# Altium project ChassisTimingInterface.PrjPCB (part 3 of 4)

## Sheet FPGA_ARTIX7.SchDoc: FPGA
size C; Organization: Altium Limited; Address1: L3, 12a Rodborough Rd; Address2: Frenchs Forest; Address3: NSW; Address4: Australia 2086; DocumentNumber: 7; SheetNumber: 6; SheetTotal: 12
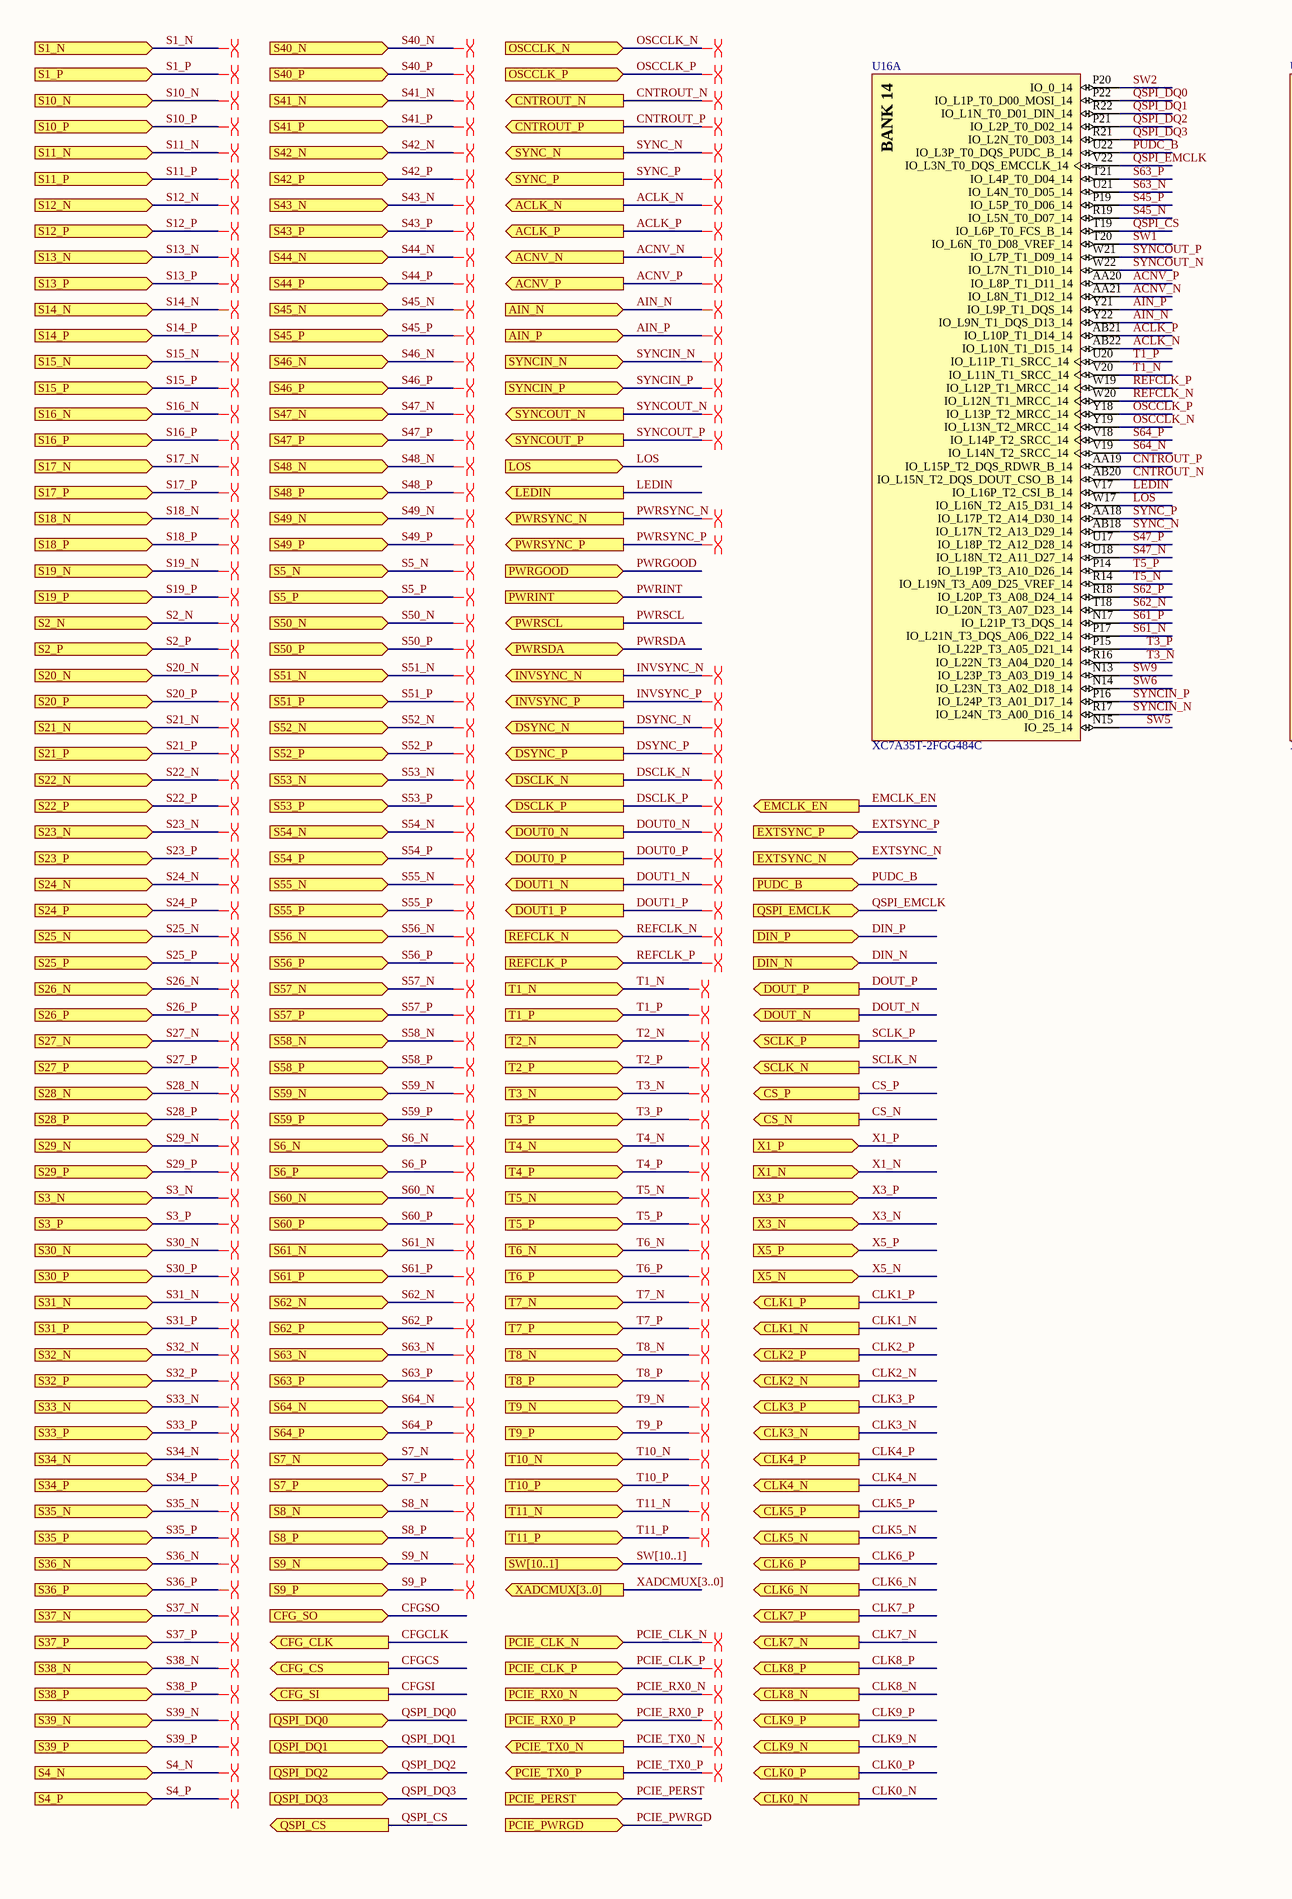
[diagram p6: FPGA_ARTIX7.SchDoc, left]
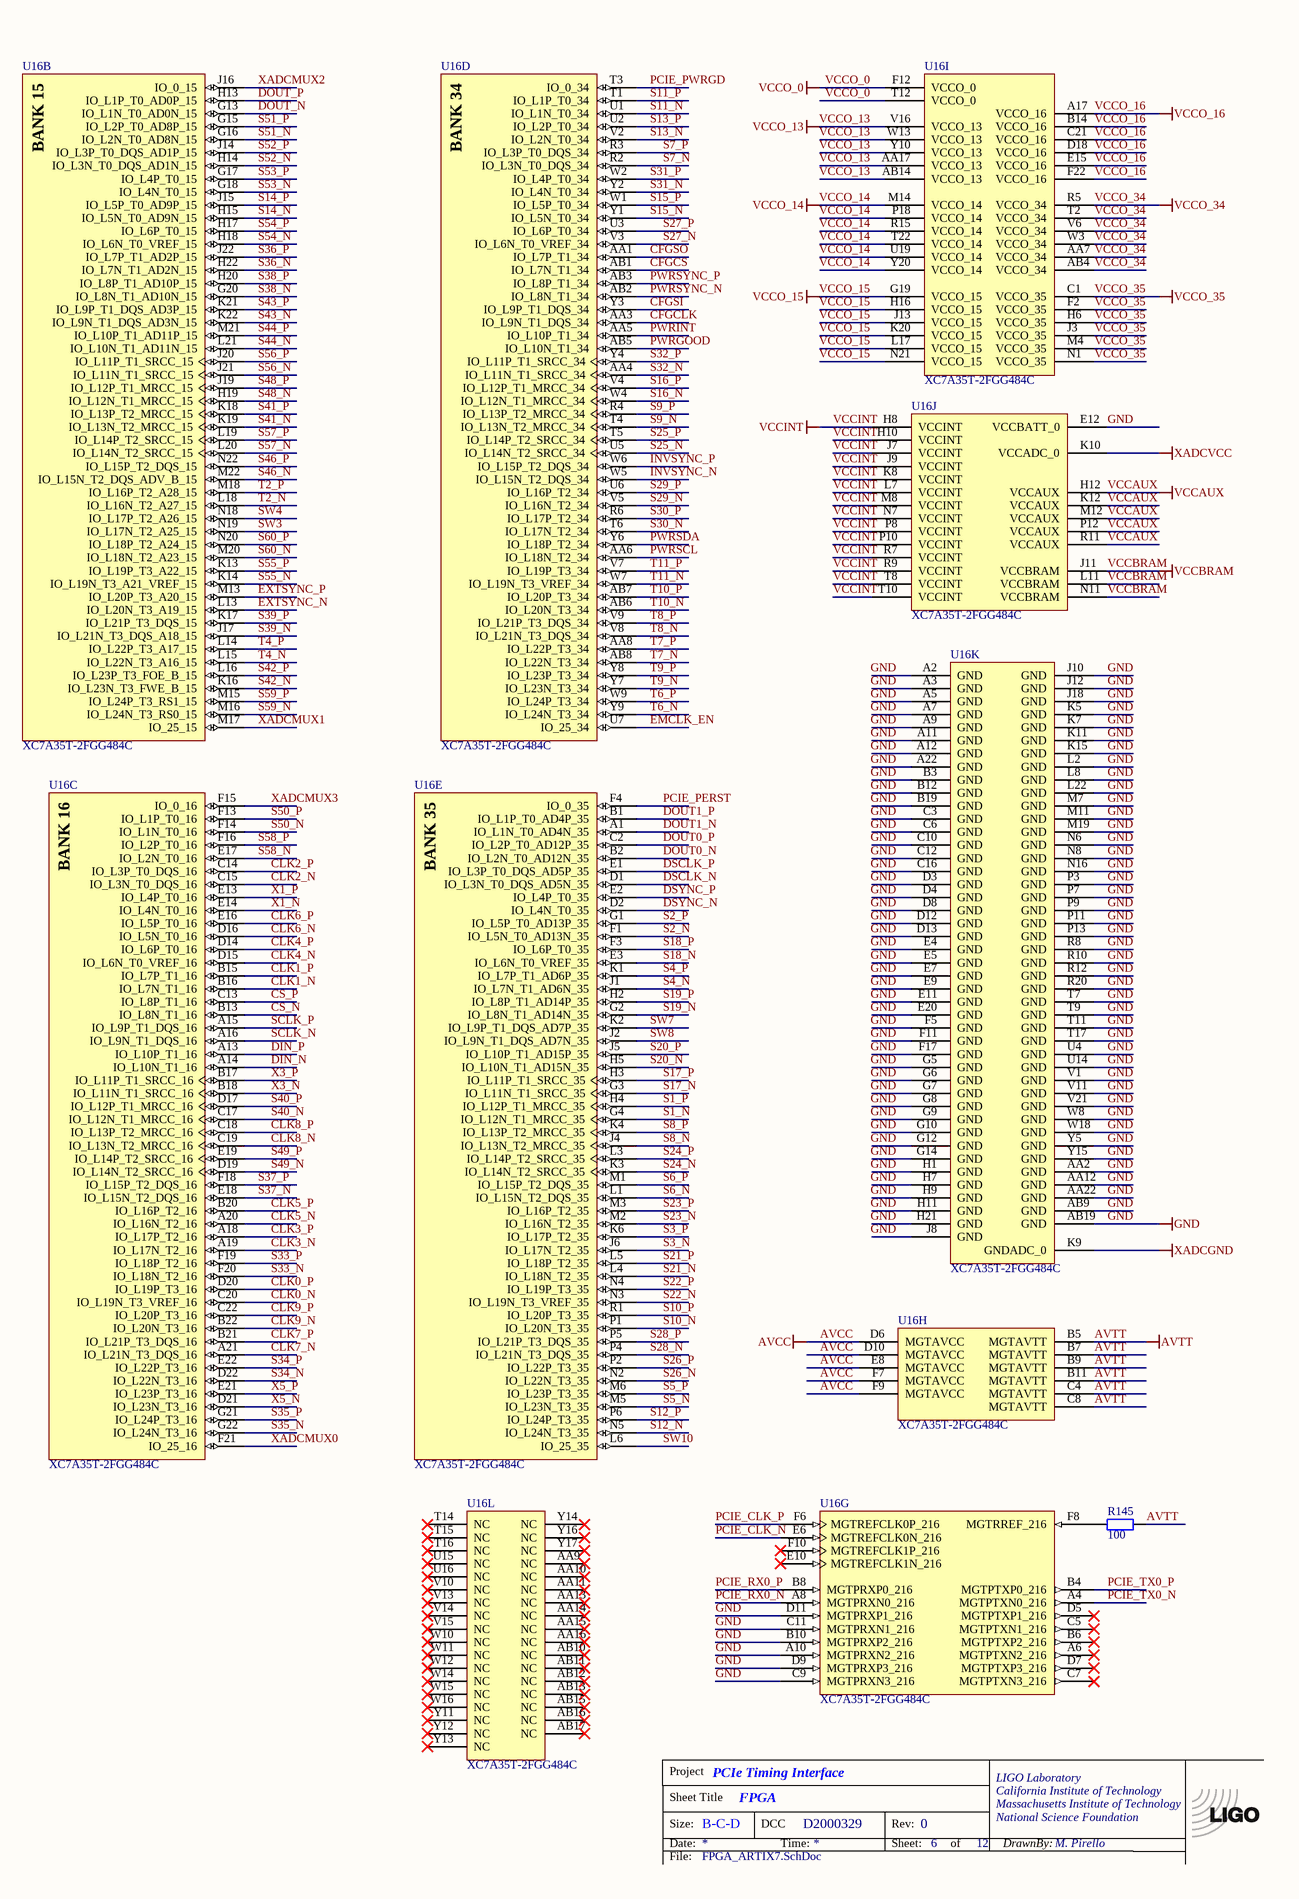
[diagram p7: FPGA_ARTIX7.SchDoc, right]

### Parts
(Parts that share a designator on the sheet are numbered #1, #2 ... from top to bottom, then left to right.)
*?#4  TitleBlock  (value not drawn)  (graphical)
R145  100  [CR1608-0603]
U16  XC7A35T-2FGG484C  [FGG484]  (parts A,B,C,D,E,G,H,I,J,K,L of 12)

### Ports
ACLK_N (out), ACLK_P (out), ACNV_N (out), ACNV_P (out), AIN_N (in), AIN_P (in), CFG_CLK (out), CFG_CS (out), CFG_SI (out), CFG_SO (in), CLK0_N (out), CLK0_P (out), CLK1_N (out), CLK1_P (out), CLK2_N (out), CLK2_P (out), CLK3_N (out), CLK3_P (out), CLK4_N (out), CLK4_P (out), CLK5_N (out), CLK5_P (out), CLK6_N (out), CLK6_P (out), CLK7_N (out), CLK7_P (out), CLK8_N (out), CLK8_P (out), CLK9_N (out), CLK9_P (out), CNTROUT_N (out), CNTROUT_P (out), CS_N (out), CS_P (out), DIN_N (in), DIN_P (in), DOUT0_N (out), DOUT0_P (out), DOUT1_N (out), DOUT1_P (out), DOUT_N (out), DOUT_P (out), DSCLK_N (out), DSCLK_P (out), DSYNC_N (out), DSYNC_P (out), EMCLK_EN (out), EXTSYNC_N (in), EXTSYNC_P (in), INVSYNC_N (out), INVSYNC_P (out), LEDIN (out), LOS (in), OSCCLK_N (in), OSCCLK_P (in), PCIE_CLK_N (in), PCIE_CLK_P (in), PCIE_PERST (in), PCIE_PWRGD (in), PCIE_RX0_N (in), PCIE_RX0_P (in), PCIE_TX0_N (out), PCIE_TX0_P (out), PUDC_B (in), PWRGOOD (in), PWRINT (in), PWRSCL (out), PWRSDA (bidir), PWRSYNC_N (out), PWRSYNC_P (out), QSPI_CS (out), QSPI_DQ0 (in), QSPI_DQ1 (in), QSPI_DQ2 (in), QSPI_DQ3 (in), QSPI_EMCLK (in), REFCLK_N (in), REFCLK_P (in), S1_N (in), S1_P (in), S2_N (in), S2_P (in), S3_N (in), S3_P (in), S4_N (in), S4_P (in), S5_N (in), S5_P (in), S6_N (in), S6_P (in), S7_N (in), S7_P (in), S8_N (in), S8_P (in), S9_N (in), S9_P (in), S10_N (in), S10_P (in), S11_N (in), S11_P (in), S12_N (in), S12_P (in), S13_N (in), S13_P (in), S14_N (in), S14_P (in), S15_N (in), S15_P (in), S16_N (in), S16_P (in), S17_N (in), S17_P (in), S18_N (in), S18_P (in), S19_N (in), S19_P (in), S20_N (in), S20_P (in), S21_N (in), S21_P (in), S22_N (in), S22_P (in), S23_N (in), S23_P (in), S24_N (in), S24_P (in), S25_N (in), S25_P (in), S26_N (in), S26_P (in), S27_N (in), S27_P (in), S28_N (in), S28_P (in), S29_N (in), S29_P (in), S30_N (in), S30_P (in), S31_N (in), S31_P (in), S32_N (in), S32_P (in), S33_N (in), S33_P (in), S34_N (in), S34_P (in), S35_N (in), S35_P (in), S36_N (in), S36_P (in), S37_N (in), S37_P (in), S38_N (in), S38_P (in), S39_N (in), S39_P (in), S40_N (in), S40_P (in), S41_N (in), S41_P (in), S42_N (in), S42_P (in), S43_N (in), S43_P (in), S44_N (in), S44_P (in), S45_N (in), S45_P (in), S46_N (in), S46_P (in), S47_N (in), S47_P (in), S48_N (in), S48_P (in), S49_N (in), S49_P (in), S50_N (in), S50_P (in), S51_N (in), S51_P (in), S52_N (in), S52_P (in), S53_N (in), S53_P (in), S54_N (in), S54_P (in), S55_N (in), S55_P (in), S56_N (in), S56_P (in), S57_N (in), S57_P (in), S58_N (in), S58_P (in), S59_N (in), S59_P (in), S60_N (in), S60_P (in), S61_N (in), S61_P (in), S62_N (in), S62_P (in), S63_N (in), S63_P (in), S64_N (in), S64_P (in), SCLK_N (out), SCLK_P (out), SW[10..1] (in), SYNC_N (out), SYNC_P (out), SYNCIN_N (in), SYNCIN_P (in), SYNCOUT_N (out), SYNCOUT_P (out), T1_N (in), T1_P (in), T2_N (in), T2_P (in), T3_N (in), T3_P (in), T4_N (in), T4_P (in), T5_N (in), T5_P (in), T6_N (in), T6_P (in), T7_N (in), T7_P (in), T8_N (in), T8_P (in), T9_N (in), T9_P (in), T10_N (in), T10_P (in), T11_N (in), T11_P (in), X1_N (in), X1_P (in), X3_N (in), X3_P (in), X5_N (in), X5_P (in), XADCMUX[3..0] (out)

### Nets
AVCC: U16.D6(MGTAVCC) U16.D10(MGTAVCC) U16.E8(MGTAVCC) U16.F7(MGTAVCC) U16.F9(MGTAVCC)
AVTT: R145.2 U16.B5(MGTAVTT) U16.B7(MGTAVTT) U16.B9(MGTAVTT) U16.B11(MGTAVTT) U16.C4(MGTAVTT) U16.C8(MGTAVTT)
GND: U16.A2(GND) U16.A3(GND) U16.A5(GND) U16.A7(GND) U16.A9(GND) U16.A10(MGTPRXN2_216) U16.A11(GND) U16.A12(GND) U16.A22(GND) U16.AA2(GND) U16.AA12(GND) U16.AA22(GND) U16.AB9(GND) U16.AB19(GND) U16.B3(GND) U16.B10(MGTPRXP2_216) U16.B12(GND) U16.B19(GND) U16.C3(GND) U16.C6(GND) U16.C9(MGTPRXN3_216) U16.C10(GND) U16.C11(MGTPRXN1_216) U16.C12(GND) U16.C16(GND) U16.D3(GND) U16.D4(GND) U16.D8(GND) U16.D9(MGTPRXP3_216) U16.D11(MGTPRXP1_216) U16.D12(GND) U16.D13(GND) U16.E4(GND) U16.E5(GND) U16.E7(GND) U16.E9(GND) U16.E11(GND) U16.E12(VCCBATT_0) U16.E20(GND) U16.F5(GND) U16.F11(GND) U16.F17(GND) U16.G5(GND) U16.G6(GND) U16.G7(GND) U16.G8(GND) U16.G9(GND) U16.G10(GND) U16.G12(GND) U16.G14(GND) U16.H1(GND) U16.H7(GND) U16.H9(GND) U16.H11(GND) U16.H21(GND) U16.J8(GND) U16.J10(GND) U16.J12(GND) U16.J18(GND) U16.K5(GND) U16.K7(GND) U16.K11(GND) U16.K15(GND) U16.L2(GND) U16.L8(GND) U16.L22(GND) U16.M7(GND) U16.M11(GND) U16.M19(GND) U16.N6(GND) U16.N8(GND) U16.N16(GND) U16.P3(GND) U16.P7(GND) U16.P9(GND) U16.P11(GND) U16.P13(GND) U16.R8(GND) U16.R10(GND) U16.R12(GND) U16.R20(GND) U16.T7(GND) U16.T9(GND) U16.T11(GND) U16.T17(GND) U16.U4(GND) U16.U14(GND) U16.V1(GND) U16.V11(GND) U16.V21(GND) U16.W8(GND) U16.W18(GND) U16.Y5(GND) U16.Y15(GND)
VCCAUX: U16.H12(VCCAUX) U16.K12(VCCAUX) U16.M12(VCCAUX) U16.P12(VCCAUX) U16.R11(VCCAUX)  [project net VCC1V8]
VCCINT: U16.H8(VCCINT) U16.H10(VCCINT) U16.J7(VCCINT) U16.J9(VCCINT) U16.J11(VCCBRAM) U16.K8(VCCINT) U16.L7(VCCINT) U16.L11(VCCBRAM) U16.M8(VCCINT) U16.N7(VCCINT) U16.N11(VCCBRAM) U16.P8(VCCINT) U16.P10(VCCINT) U16.R7(VCCINT) U16.R9(VCCINT) U16.T8(VCCINT) U16.T10(VCCINT)  [also labelled VCCBRAM]
VCCO_0: U16.A17(VCCO_16) U16.AA7(VCCO_34) U16.AA17(VCCO_13) U16.AB4(VCCO_34) U16.AB14(VCCO_13) U16.B14(VCCO_16) U16.C1(VCCO_35) U16.C21(VCCO_16) U16.D18(VCCO_16) U16.E15(VCCO_16) U16.F2(VCCO_35) U16.F12(VCCO_0) U16.F22(VCCO_16) U16.G19(VCCO_15) U16.H6(VCCO_35) U16.H16(VCCO_15) U16.J3(VCCO_35) U16.J13(VCCO_15) U16.K20(VCCO_15) U16.L17(VCCO_15) U16.M4(VCCO_35) U16.M14(VCCO_14) U16.N1(VCCO_35) U16.N21(VCCO_15) U16.P18(VCCO_14) U16.R5(VCCO_34) U16.R15(VCCO_14) U16.T2(VCCO_34) U16.T12(VCCO_0) U16.T22(VCCO_14) U16.U19(VCCO_14) U16.V6(VCCO_34) U16.V16(VCCO_13) U16.W3(VCCO_34) U16.W13(VCCO_13) U16.Y10(VCCO_13) U16.Y20(VCCO_14)  [also labelled VCCO_13, VCCO_14, VCCO_15, VCCO_16, VCCO_34, VCCO_35]  [project net VDD]
XADCGND: U16.K9(GNDADC_0)
XADCVCC: U16.K10(VCCADC_0)
ACLK_N: U16.AB22(IO_L10N_T1_D15_14) ; port ACLK_N  [project net CLOCK.ACLK_N]
ACLK_P: U16.AB21(IO_L10P_T1_D14_14) ; port ACLK_P  [project net CLOCK.ACLK_P]
ACNV_N: U16.AA21(IO_L8N_T1_D12_14) ; port ACNV_N  [project net CLOCK.ACNV_N]
ACNV_P: U16.AA20(IO_L8P_T1_D11_14) ; port ACNV_P  [project net CLOCK.ACNV_P]
AIN_N: U16.Y22(IO_L9N_T1_DQS_D13_14) ; port AIN_N  [project net CLOCK.AIN_N]
AIN_P: U16.Y21(IO_L9P_T1_DQS_14) ; port AIN_P  [project net CLOCK.AIN_P]
CFGCLK: U16.AA3(IO_L9N_T1_DQS_34) ; port CFG_CLK  [project net CFG_CLK]
CFGCS: U16.AB1(IO_L7N_T1_34) ; port CFG_CS  [project net CFG_CS]
CFGSI: U16.Y3(IO_L9P_T1_DQS_34) ; port CFG_SI  [project net CFG_SI]
CFGSO: U16.AA1(IO_L7P_T1_34) ; port CFG_SO  [project net CFG_SO]
CLK0_N: U16.C20(IO_L19N_T3_VREF_16) ; port CLK0_N  [project net BACKPLANE.CLK0_N]
CLK0_P: U16.D20(IO_L19P_T3_16) ; port CLK0_P  [project net BACKPLANE.CLK0_P]
CLK1_N: U16.B16(IO_L7N_T1_16) ; port CLK1_N  [project net BACKPLANE.CLK1_N]
CLK1_P: U16.B15(IO_L7P_T1_16) ; port CLK1_P  [project net BACKPLANE.CLK1_P]
CLK2_N: U16.C15(IO_L3N_T0_DQS_16) ; port CLK2_N  [project net BACKPLANE.CLK2_N]
CLK2_P: U16.C14(IO_L3P_T0_DQS_16) ; port CLK2_P  [project net BACKPLANE.CLK2_P]
CLK3_N: U16.A19(IO_L17N_T2_16) ; port CLK3_N  [project net BACKPLANE.CLK3_N]
CLK3_P: U16.A18(IO_L17P_T2_16) ; port CLK3_P  [project net BACKPLANE.CLK3_P]
CLK4_N: U16.D15(IO_L6N_T0_VREF_16) ; port CLK4_N  [project net BACKPLANE.CLK4_N]
CLK4_P: U16.D14(IO_L6P_T0_16) ; port CLK4_P  [project net BACKPLANE.CLK4_P]
CLK5_N: U16.A20(IO_L16N_T2_16) ; port CLK5_N  [project net BACKPLANE.CLK5_N]
CLK5_P: U16.B20(IO_L16P_T2_16) ; port CLK5_P  [project net BACKPLANE.CLK5_P]
CLK6_N: U16.D16(IO_L5N_T0_16) ; port CLK6_N  [project net BACKPLANE.CLK6_N]
CLK6_P: U16.E16(IO_L5P_T0_16) ; port CLK6_P  [project net BACKPLANE.CLK6_P]
CLK7_N: U16.A21(IO_L21N_T3_DQS_16) ; port CLK7_N  [project net BACKPLANE.CLK7_N]
CLK7_P: U16.B21(IO_L21P_T3_DQS_16) ; port CLK7_P  [project net BACKPLANE.CLK7_P]
CLK8_N: U16.C19(IO_L13N_T2_MRCC_16) ; port CLK8_N  [project net BACKPLANE.CLK8_N]
CLK8_P: U16.C18(IO_L13P_T2_MRCC_16) ; port CLK8_P  [project net BACKPLANE.CLK8_P]
CLK9_N: U16.B22(IO_L20N_T3_16) ; port CLK9_N  [project net BACKPLANE.CLK9_N]
CLK9_P: U16.C22(IO_L20P_T3_16) ; port CLK9_P  [project net BACKPLANE.CLK9_P]
CNTROUT_N: U16.AB20(IO_L15N_T2_DQS_DOUT_CSO_B_14) ; port CNTROUT_N  [project net CLOCK.CNTROUT_N]
CNTROUT_P: U16.AA19(IO_L15P_T2_DQS_RDWR_B_14) ; port CNTROUT_P  [project net CLOCK.CNTROUT_P]
CS_N: U16.B13(IO_L8N_T1_16) ; port CS_N  [project net BACKPLANE.CS_N]
CS_P: U16.C13(IO_L8P_T1_16) ; port CS_P  [project net BACKPLANE.CS_P]
DIN_N: U16.A14(IO_L10N_T1_16) ; port DIN_N  [project net BACKPLANE.DIN_N]
DIN_P: U16.A13(IO_L10P_T1_16) ; port DIN_P  [project net BACKPLANE.DIN_P]
DOUT0_N: U16.B2(IO_L2N_T0_AD12N_35) ; port DOUT0_N  [project net DAC_REF.DOUT0_N]
DOUT0_P: U16.C2(IO_L2P_T0_AD12P_35) ; port DOUT0_P  [project net DAC_REF.DOUT0_P]
DOUT1_N: U16.A1(IO_L1N_T0_AD4N_35) ; port DOUT1_N  [project net DAC_REF.DOUT1_N]
DOUT1_P: U16.B1(IO_L1P_T0_AD4P_35) ; port DOUT1_P  [project net DAC_REF.DOUT1_P]
DOUT_N: U16.G13(IO_L1N_T0_AD0N_15) ; port DOUT_N  [project net BACKPLANE.DOUT_N]
DOUT_P: U16.H13(IO_L1P_T0_AD0P_15) ; port DOUT_P  [project net BACKPLANE.DOUT_P]
DSCLK_N: U16.D1(IO_L3N_T0_DQS_AD5N_35) ; port DSCLK_N  [project net DAC_REF.DSCLK_N]
DSCLK_P: U16.E1(IO_L3P_T0_DQS_AD5P_35) ; port DSCLK_P  [project net DAC_REF.DSCLK_P]
DSYNC_N: U16.D2(IO_L4N_T0_35) ; port DSYNC_N  [project net DAC_REF.DSYNC_N]
DSYNC_P: U16.E2(IO_L4P_T0_35) ; port DSYNC_P  [project net DAC_REF.DSYNC_P]
EMCLK_EN: U16.U7(IO_25_34) ; port EMCLK_EN  [project net SQSPI.EMCLK_EN]
EXTSYNC_N: U16.L13(IO_L20N_T3_A19_15) ; port EXTSYNC_N  [project net EXT_SYNC.EXTSYNC_N]
EXTSYNC_P: U16.M13(IO_L20P_T3_A20_15) ; port EXTSYNC_P  [project net EXT_SYNC.EXTSYNC_P]
INVSYNC_N: U16.W5(IO_L15N_T2_DQS_34) ; port INVSYNC_N  [project net DAC_REF.INVSYNC_N]
INVSYNC_P: U16.W6(IO_L15P_T2_DQS_34) ; port INVSYNC_P  [project net DAC_REF.INVSYNC_P]
LEDIN: U16.V17(IO_L16P_T2_CSI_B_14) ; port LEDIN  [project net SFPIN.LEDIN]
LOS: U16.W17(IO_L16N_T2_A15_D31_14) ; port LOS  [project net SFPIN.LOS]
OSCCLK_N: U16.Y19(IO_L13N_T2_MRCC_14) ; port OSCCLK_N  [project net CLOCK.OSCCLK_N]
OSCCLK_P: U16.Y18(IO_L13P_T2_MRCC_14) ; port OSCCLK_P  [project net CLOCK.OSCCLK_P]
PCIE_CLK_N: U16.E6(MGTREFCLK0N_216) ; port PCIE_CLK_N  [project net PCIE.PCIE_CLK_N]
PCIE_CLK_P: U16.F6(MGTREFCLK0P_216) ; port PCIE_CLK_P  [project net PCIE.PCIE_CLK_P]
PCIE_PERST: U16.F4(IO_0_35) ; port PCIE_PERST  [project net PCIE.PCIE_PERST]
PCIE_PWRGD: U16.T3(IO_0_34) ; port PCIE_PWRGD  [project net PCIE.PCIE_PWRGD]
PCIE_RX0_N: U16.A8(MGTPRXN0_216) ; port PCIE_RX0_N  [project net PCIE.PCIE_RX0_N]
PCIE_RX0_P: U16.B8(MGTPRXP0_216) ; port PCIE_RX0_P  [project net PCIE.PCIE_RX0_P]
PCIE_TX0_N: U16.A4(MGTPTXN0_216) ; port PCIE_TX0_N  [project net PCIE.PCIE_TX0_N]
PCIE_TX0_P: U16.B4(MGTPTXP0_216) ; port PCIE_TX0_P  [project net PCIE.PCIE_TX0_P]
PUDC_B: U16.U22(IO_L3P_T0_DQS_PUDC_B_14) ; port PUDC_B  [project net SQSPI.PUDC_B]
PWRGOOD: U16.AB5(IO_L10N_T1_34) ; port PWRGOOD  [project net POWER.PWRGOOD]
PWRINT: U16.AA5(IO_L10P_T1_34) ; port PWRINT  [project net POWER.PWRINT]
PWRSCL: U16.AA6(IO_L18N_T2_34) ; port PWRSCL  [project net POWER.PWRSCL]
PWRSDA: U16.Y6(IO_L18P_T2_34) ; port PWRSDA  [project net POWER.PWRSDA]
PWRSYNC_N: U16.AB2(IO_L8N_T1_34) ; port PWRSYNC_N  [project net POWER.PWRSYNC_N]
PWRSYNC_P: U16.AB3(IO_L8P_T1_34) ; port PWRSYNC_P  [project net POWER.PWRSYNC_P]
QSPI_CS: U16.T19(IO_L6P_T0_FCS_B_14) ; port QSPI_CS  [project net SQSPI.QSPI_CS]
QSPI_DQ0: U16.P22(IO_L1P_T0_D00_MOSI_14) ; port QSPI_DQ0  [project net SQSPI.QSPI_DQ0]
QSPI_DQ1: U16.R22(IO_L1N_T0_D01_DIN_14) ; port QSPI_DQ1  [project net SQSPI.QSPI_DQ1]
QSPI_DQ2: U16.P21(IO_L2P_T0_D02_14) ; port QSPI_DQ2  [project net SQSPI.QSPI_DQ2]
QSPI_DQ3: U16.R21(IO_L2N_T0_D03_14) ; port QSPI_DQ3  [project net SQSPI.QSPI_DQ3]
QSPI_EMCLK: U16.V22(IO_L3N_T0_DQS_EMCCLK_14) ; port QSPI_EMCLK  [project net SQSPI.QSPI_EMCLK]
REFCLK_N: U16.W20(IO_L12N_T1_MRCC_14) ; port REFCLK_N  [project net DAC_REF.REFCLK_N]
REFCLK_P: U16.W19(IO_L12P_T1_MRCC_14) ; port REFCLK_P  [project net DAC_REF.REFCLK_P]
S1_N: U16.G4(IO_L12N_T1_MRCC_35) ; port S1_N  [project net S1_16.S1_N]
S1_P: U16.H4(IO_L12P_T1_MRCC_35) ; port S1_P  [project net S1_16.S1_P]
S2_N: U16.F1(IO_L5N_T0_AD13N_35) ; port S2_N  [project net S1_16.S2_N]
S2_P: U16.G1(IO_L5P_T0_AD13P_35) ; port S2_P  [project net S1_16.S2_P]
S3_N: U16.J6(IO_L17N_T2_35) ; port S3_N  [project net S1_16.S3_N]
S3_P: U16.K6(IO_L17P_T2_35) ; port S3_P  [project net S1_16.S3_P]
S4_N: U16.J1(IO_L7N_T1_AD6N_35) ; port S4_N  [project net S1_16.S4_N]
S4_P: U16.K1(IO_L7P_T1_AD6P_35) ; port S4_P  [project net S1_16.S4_P]
S5_N: U16.M5(IO_L23N_T3_35) ; port S5_N  [project net S1_16.S5_N]
S5_P: U16.M6(IO_L23P_T3_35) ; port S5_P  [project net S1_16.S5_P]
S6_N: U16.L1(IO_L15N_T2_DQS_35) ; port S6_N  [project net S1_16.S6_N]
S6_P: U16.M1(IO_L15P_T2_DQS_35) ; port S6_P  [project net S1_16.S6_P]
S7_N: U16.R2(IO_L3N_T0_DQS_34) ; port S7_N  [project net S1_16.S7_N]
S7_P: U16.R3(IO_L3P_T0_DQS_34) ; port S7_P  [project net S1_16.S7_P]
S8_N: U16.J4(IO_L13N_T2_MRCC_35) ; port S8_N  [project net S1_16.S8_N]
S8_P: U16.K4(IO_L13P_T2_MRCC_35) ; port S8_P  [project net S1_16.S8_P]
S9_N: U16.T4(IO_L13N_T2_MRCC_34) ; port S9_N  [project net S1_16.S9_N]
S9_P: U16.R4(IO_L13P_T2_MRCC_34) ; port S9_P  [project net S1_16.S9_P]
S10_N: U16.P1(IO_L20N_T3_35) ; port S10_N
S10_P: U16.R1(IO_L20P_T3_35) ; port S10_P
S11_N: U16.U1(IO_L1N_T0_34) ; port S11_N
S11_P: U16.T1(IO_L1P_T0_34) ; port S11_P
S12_N: U16.N5(IO_L24N_T3_35) ; port S12_N
S12_P: U16.P6(IO_L24P_T3_35) ; port S12_P
S13_N: U16.V2(IO_L2N_T0_34) ; port S13_N
S13_P: U16.U2(IO_L2P_T0_34) ; port S13_P
S14_N: U16.H15(IO_L5N_T0_AD9N_15) ; port S14_N
S14_P: U16.J15(IO_L5P_T0_AD9P_15) ; port S14_P
S15_N: U16.Y1(IO_L5N_T0_34) ; port S15_N
S15_P: U16.W1(IO_L5P_T0_34) ; port S15_P
S16_N: U16.W4(IO_L12N_T1_MRCC_34) ; port S16_N
S16_P: U16.V4(IO_L12P_T1_MRCC_34) ; port S16_P
S17_N: U16.G3(IO_L11N_T1_SRCC_35) ; port S17_N  [project net S17_32.S17_N]
S17_P: U16.H3(IO_L11P_T1_SRCC_35) ; port S17_P  [project net S17_32.S17_P]
S18_N: U16.E3(IO_L6N_T0_VREF_35) ; port S18_N  [project net S17_32.S18_N]
S18_P: U16.F3(IO_L6P_T0_35) ; port S18_P  [project net S17_32.S18_P]
S19_N: U16.G2(IO_L8N_T1_AD14N_35) ; port S19_N  [project net S17_32.S19_N]
S19_P: U16.H2(IO_L8P_T1_AD14P_35) ; port S19_P  [project net S17_32.S19_P]
S20_N: U16.H5(IO_L10N_T1_AD15N_35) ; port S20_N  [project net S17_32.S20_N]
S20_P: U16.J5(IO_L10P_T1_AD15P_35) ; port S20_P  [project net S17_32.S20_P]
S21_N: U16.L4(IO_L18N_T2_35) ; port S21_N  [project net S17_32.S21_N]
S21_P: U16.L5(IO_L18P_T2_35) ; port S21_P  [project net S17_32.S21_P]
S22_N: U16.N3(IO_L19N_T3_VREF_35) ; port S22_N  [project net S17_32.S22_N]
S22_P: U16.N4(IO_L19P_T3_35) ; port S22_P  [project net S17_32.S22_P]
S23_N: U16.M2(IO_L16N_T2_35) ; port S23_N  [project net S17_32.S23_N]
S23_P: U16.M3(IO_L16P_T2_35) ; port S23_P  [project net S17_32.S23_P]
S24_N: U16.K3(IO_L14N_T2_SRCC_35) ; port S24_N  [project net S17_32.S24_N]
S24_P: U16.L3(IO_L14P_T2_SRCC_35) ; port S24_P  [project net S17_32.S24_P]
S25_N: U16.U5(IO_L14N_T2_SRCC_34) ; port S25_N  [project net S17_32.S25_N]
S25_P: U16.T5(IO_L14P_T2_SRCC_34) ; port S25_P  [project net S17_32.S25_P]
S26_N: U16.N2(IO_L22N_T3_35) ; port S26_N  [project net S17_32.S26_N]
S26_P: U16.P2(IO_L22P_T3_35) ; port S26_P  [project net S17_32.S26_P]
S27_N: U16.V3(IO_L6N_T0_VREF_34) ; port S27_N  [project net S17_32.S27_N]
S27_P: U16.U3(IO_L6P_T0_34) ; port S27_P  [project net S17_32.S27_P]
S28_N: U16.P4(IO_L21N_T3_DQS_35) ; port S28_N  [project net S17_32.S28_N]
S28_P: U16.P5(IO_L21P_T3_DQS_35) ; port S28_P  [project net S17_32.S28_P]
S29_N: U16.V5(IO_L16N_T2_34) ; port S29_N  [project net S17_32.S29_N]
S29_P: U16.U6(IO_L16P_T2_34) ; port S29_P  [project net S17_32.S29_P]
S30_N: U16.T6(IO_L17N_T2_34) ; port S30_N  [project net S17_32.S30_N]
S30_P: U16.R6(IO_L17P_T2_34) ; port S30_P  [project net S17_32.S30_P]
S31_N: U16.Y2(IO_L4N_T0_34) ; port S31_N  [project net S17_32.S31_N]
S31_P: U16.W2(IO_L4P_T0_34) ; port S31_P  [project net S17_32.S31_P]
S32_N: U16.AA4(IO_L11N_T1_SRCC_34) ; port S32_N  [project net S17_32.S32_N]
S32_P: U16.Y4(IO_L11P_T1_SRCC_34) ; port S32_P  [project net S17_32.S32_P]
S33_N: U16.F20(IO_L18N_T2_16) ; port S33_N  [project net S33_48.S33_N]
S33_P: U16.F19(IO_L18P_T2_16) ; port S33_P  [project net S33_48.S33_P]
S34_N: U16.D22(IO_L22N_T3_16) ; port S34_N  [project net S33_48.S34_N]
S34_P: U16.E22(IO_L22P_T3_16) ; port S34_P  [project net S33_48.S34_P]
S35_N: U16.G22(IO_L24N_T3_16) ; port S35_N  [project net S33_48.S35_N]
S35_P: U16.G21(IO_L24P_T3_16) ; port S35_P  [project net S33_48.S35_P]
S36_N: U16.H22(IO_L7N_T1_AD2N_15) ; port S36_N  [project net S33_48.S36_N]
S36_P: U16.J22(IO_L7P_T1_AD2P_15) ; port S36_P  [project net S33_48.S36_P]
S37_N: U16.E18(IO_L15N_T2_DQS_16) ; port S37_N  [project net S33_48.S37_N]
S37_P: U16.F18(IO_L15P_T2_DQS_16) ; port S37_P  [project net S33_48.S37_P]
S38_N: U16.G20(IO_L8N_T1_AD10N_15) ; port S38_N  [project net S33_48.S38_N]
S38_P: U16.H20(IO_L8P_T1_AD10P_15) ; port S38_P  [project net S33_48.S38_P]
S39_N: U16.J17(IO_L21N_T3_DQS_A18_15) ; port S39_N  [project net S33_48.S39_N]
S39_P: U16.K17(IO_L21P_T3_DQS_15) ; port S39_P  [project net S33_48.S39_P]
S40_N: U16.C17(IO_L12N_T1_MRCC_16) ; port S40_N  [project net S33_48.S40_N]
S40_P: U16.D17(IO_L12P_T1_MRCC_16) ; port S40_P  [project net S33_48.S40_P]
S41_N: U16.K19(IO_L13N_T2_MRCC_15) ; port S41_N  [project net S33_48.S41_N]
S41_P: U16.K18(IO_L13P_T2_MRCC_15) ; port S41_P  [project net S33_48.S41_P]
S42_N: U16.K16(IO_L23N_T3_FWE_B_15) ; port S42_N  [project net S33_48.S42_N]
S42_P: U16.L16(IO_L23P_T3_FOE_B_15) ; port S42_P  [project net S33_48.S42_P]
S43_N: U16.K22(IO_L9N_T1_DQS_AD3N_15) ; port S43_N  [project net S33_48.S43_N]
S43_P: U16.K21(IO_L9P_T1_DQS_AD3P_15) ; port S43_P  [project net S33_48.S43_P]
S44_N: U16.L21(IO_L10N_T1_AD11N_15) ; port S44_N  [project net S33_48.S44_N]
S44_P: U16.M21(IO_L10P_T1_AD11P_15) ; port S44_P  [project net S33_48.S44_P]
S45_N: U16.R19(IO_L5N_T0_D07_14) ; port S45_N  [project net S33_48.S45_N]
S45_P: U16.P19(IO_L5P_T0_D06_14) ; port S45_P  [project net S33_48.S45_P]
S46_N: U16.M22(IO_L15N_T2_DQS_ADV_B_15) ; port S46_N  [project net S33_48.S46_N]
S46_P: U16.N22(IO_L15P_T2_DQS_15) ; port S46_P  [project net S33_48.S46_P]
S47_N: U16.U18(IO_L18N_T2_A11_D27_14) ; port S47_N  [project net S33_48.S47_N]
S47_P: U16.U17(IO_L18P_T2_A12_D28_14) ; port S47_P  [project net S33_48.S47_P]
S48_N: U16.H19(IO_L12N_T1_MRCC_15) ; port S48_N  [project net S33_48.S48_N]
S48_P: U16.J19(IO_L12P_T1_MRCC_15) ; port S48_P  [project net S33_48.S48_P]
S49_N: U16.D19(IO_L14N_T2_SRCC_16) ; port S49_N  [project net S49_64.S49_N]
S49_P: U16.E19(IO_L14P_T2_SRCC_16) ; port S49_P  [project net S49_64.S49_P]
S50_N: U16.F14(IO_L1N_T0_16) ; port S50_N  [project net S49_64.S50_N]
S50_P: U16.F13(IO_L1P_T0_16) ; port S50_P  [project net S49_64.S50_P]
S51_N: U16.G16(IO_L2N_T0_AD8N_15) ; port S51_N  [project net S49_64.S51_N]
S51_P: U16.G15(IO_L2P_T0_AD8P_15) ; port S51_P  [project net S49_64.S51_P]
S52_N: U16.H14(IO_L3N_T0_DQS_AD1N_15) ; port S52_N  [project net S49_64.S52_N]
S52_P: U16.J14(IO_L3P_T0_DQS_AD1P_15) ; port S52_P  [project net S49_64.S52_P]
S53_N: U16.G18(IO_L4N_T0_15) ; port S53_N  [project net S49_64.S53_N]
S53_P: U16.G17(IO_L4P_T0_15) ; port S53_P  [project net S49_64.S53_P]
S54_N: U16.H18(IO_L6N_T0_VREF_15) ; port S54_N  [project net S49_64.S54_N]
S54_P: U16.H17(IO_L6P_T0_15) ; port S54_P  [project net S49_64.S54_P]
S55_N: U16.K14(IO_L19N_T3_A21_VREF_15) ; port S55_N  [project net S49_64.S55_N]
S55_P: U16.K13(IO_L19P_T3_A22_15) ; port S55_P  [project net S49_64.S55_P]
S56_N: U16.J21(IO_L11N_T1_SRCC_15) ; port S56_N  [project net S49_64.S56_N]
S56_P: U16.J20(IO_L11P_T1_SRCC_15) ; port S56_P  [project net S49_64.S56_P]
S57_N: U16.L20(IO_L14N_T2_SRCC_15) ; port S57_N  [project net S49_64.S57_N]
S57_P: U16.L19(IO_L14P_T2_SRCC_15) ; port S57_P  [project net S49_64.S57_P]
S58_N: U16.E17(IO_L2N_T0_16) ; port S58_N  [project net S49_64.S58_N]
S58_P: U16.F16(IO_L2P_T0_16) ; port S58_P  [project net S49_64.S58_P]
S59_N: U16.M16(IO_L24N_T3_RS0_15) ; port S59_N  [project net S49_64.S59_N]
S59_P: U16.M15(IO_L24P_T3_RS1_15) ; port S59_P  [project net S49_64.S59_P]
S60_N: U16.M20(IO_L18N_T2_A23_15) ; port S60_N  [project net S49_64.S60_N]
S60_P: U16.N20(IO_L18P_T2_A24_15) ; port S60_P  [project net S49_64.S60_P]
S61_N: U16.P17(IO_L21N_T3_DQS_A06_D22_14) ; port S61_N  [project net S49_64.S61_N]
S61_P: U16.N17(IO_L21P_T3_DQS_14) ; port S61_P  [project net S49_64.S61_P]
S62_N: U16.T18(IO_L20N_T3_A07_D23_14) ; port S62_N  [project net S49_64.S62_N]
S62_P: U16.R18(IO_L20P_T3_A08_D24_14) ; port S62_P  [project net S49_64.S62_P]
S63_N: U16.U21(IO_L4N_T0_D05_14) ; port S63_N  [project net S49_64.S63_N]
S63_P: U16.T21(IO_L4P_T0_D04_14) ; port S63_P  [project net S49_64.S63_P]
S64_N: U16.V19(IO_L14N_T2_SRCC_14) ; port S64_N  [project net S49_64.S64_N]
S64_P: U16.V18(IO_L14P_T2_SRCC_14) ; port S64_P  [project net S49_64.S64_P]
SCLK_N: U16.A16(IO_L9N_T1_DQS_16) ; port SCLK_N  [project net BACKPLANE.SCLK_N]
SCLK_P: U16.A15(IO_L9P_T1_DQS_16) ; port SCLK_P  [project net BACKPLANE.SCLK_P]
SW1: U16.T20(IO_L6N_T0_D08_VREF_14)
SW2: U16.P20(IO_0_14)
SW3: U16.N19(IO_L17N_T2_A25_15)
SW4: U16.N18(IO_L17P_T2_A26_15)
SW5: U16.N15(IO_25_14)
SW6: U16.N14(IO_L23N_T3_A02_D18_14)
SW7: U16.K2(IO_L9P_T1_DQS_AD7P_35)
SW8: U16.J2(IO_L9N_T1_DQS_AD7N_35)
SW9: U16.N13(IO_L23P_T3_A03_D19_14)
SW10: U16.L6(IO_25_35)
SYNC_N: U16.AB18(IO_L17N_T2_A13_D29_14) ; port SYNC_N  [project net CLOCK.SYNC_N]
SYNC_P: U16.AA18(IO_L17P_T2_A14_D30_14) ; port SYNC_P  [project net CLOCK.SYNC_P]
SYNCIN_N: U16.R17(IO_L24N_T3_A00_D16_14) ; port SYNCIN_N  [project net SFPIN.SYNCIN_N]
SYNCIN_P: U16.P16(IO_L24P_T3_A01_D17_14) ; port SYNCIN_P  [project net SFPIN.SYNCIN_P]
SYNCOUT_N: U16.W22(IO_L7N_T1_D10_14) ; port SYNCOUT_N  [project net SFPIN.SYNCOUT_N]
SYNCOUT_P: U16.W21(IO_L7P_T1_D09_14) ; port SYNCOUT_P  [project net SFPIN.SYNCOUT_P]
T1_N: U16.V20(IO_L11N_T1_SRCC_14) ; port T1_N  [project net T1_11.T1_N]
T1_P: U16.U20(IO_L11P_T1_SRCC_14) ; port T1_P  [project net T1_11.T1_P]
T2_N: U16.L18(IO_L16N_T2_A27_15) ; port T2_N  [project net T1_11.T2_N]
T2_P: U16.M18(IO_L16P_T2_A28_15) ; port T2_P  [project net T1_11.T2_P]
T3_N: U16.R16(IO_L22N_T3_A04_D20_14) ; port T3_N  [project net T1_11.T3_N]
T3_P: U16.P15(IO_L22P_T3_A05_D21_14) ; port T3_P  [project net T1_11.T3_P]
T4_N: U16.L15(IO_L22N_T3_A16_15) ; port T4_N  [project net T1_11.T4_N]
T4_P: U16.L14(IO_L22P_T3_A17_15) ; port T4_P  [project net T1_11.T4_P]
T5_N: U16.R14(IO_L19N_T3_A09_D25_VREF_14) ; port T5_N  [project net T1_11.T5_N]
T5_P: U16.P14(IO_L19P_T3_A10_D26_14) ; port T5_P  [project net T1_11.T5_P]
T6_N: U16.Y9(IO_L24N_T3_34) ; port T6_N  [project net T1_11.T6_N]
T6_P: U16.W9(IO_L24P_T3_34) ; port T6_P  [project net T1_11.T6_P]
T7_N: U16.AB8(IO_L22N_T3_34) ; port T7_N  [project net T1_11.T7_N]
T7_P: U16.AA8(IO_L22P_T3_34) ; port T7_P  [project net T1_11.T7_P]
T8_N: U16.V8(IO_L21N_T3_DQS_34) ; port T8_N  [project net T1_11.T8_N]
T8_P: U16.V9(IO_L21P_T3_DQS_34) ; port T8_P  [project net T1_11.T8_P]
T9_N: U16.Y7(IO_L23N_T3_34) ; port T9_N  [project net T1_11.T9_N]
T9_P: U16.Y8(IO_L23P_T3_34) ; port T9_P  [project net T1_11.T9_P]
T10_N: U16.AB6(IO_L20N_T3_34) ; port T10_N
T10_P: U16.AB7(IO_L20P_T3_34) ; port T10_P
T11_N: U16.W7(IO_L19N_T3_VREF_34) ; port T11_N
T11_P: U16.V7(IO_L19P_T3_34) ; port T11_P
X1_N: U16.E14(IO_L4N_T0_16) ; port X1_N  [project net BACKPLANE.X1_N]
X1_P: U16.E13(IO_L4P_T0_16) ; port X1_P  [project net BACKPLANE.X1_P]
X3_N: U16.B18(IO_L11N_T1_SRCC_16) ; port X3_N  [project net BACKPLANE.X3_N]
X3_P: U16.B17(IO_L11P_T1_SRCC_16) ; port X3_P  [project net BACKPLANE.X3_P]
X5_N: U16.D21(IO_L23N_T3_16) ; port X5_N  [project net BACKPLANE.X5_N]
X5_P: U16.E21(IO_L23P_T3_16) ; port X5_P  [project net BACKPLANE.X5_P]
XADCMUX0: U16.F21(IO_25_16)  [project net XMUX0]
XADCMUX1: U16.M17(IO_25_15)  [project net XMUX1]
XADCMUX2: U16.J16(IO_0_15)  [project net XMUX2]
XADCMUX3: U16.F15(IO_0_16)  [project net XMUX3]
NetR145_1: R145.1 U16.F8(MGTRREF_216)

Not connected (* = marked no-connect by the designer): U16 A6(MGTPTXN2_216)* AA9(NC)* AA10(NC)* AA11(NC)* AA13(NC)* AA14(NC)* AA15(NC)* AA16(NC)* AB10(NC)* AB11(NC)* AB12(NC)* AB13(NC)* AB15(NC)* AB16(NC)* AB17(NC)* B6(MGTPTXP2_216)* C5(MGTPTXN1_216)* C7(MGTPTXN3_216)* D5(MGTPTXP1_216)* D7(MGTPTXP3_216)* E10(MGTREFCLK1N_216)* F10(MGTREFCLK1P_216)* T14(NC)* T15(NC)* T16(NC)* U15(NC)* U16(NC)* V10(NC)* V13(NC)* V14(NC)* V15(NC)* W10(NC)* W11(NC)* W12(NC)* W14(NC)* W15(NC)* W16(NC)* Y11(NC)* Y12(NC)* Y13(NC)* Y14(NC)* Y16(NC)* Y17(NC)*

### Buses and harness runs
bus SW[10..1] = port SW[10..1]
bus XADCMUX[3..0] = port XADCMUX[3..0]

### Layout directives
differential pair: CLOCK.ACLK_N, CLOCK.ACLK_P, CLOCK.ACNV_N, CLOCK.ACNV_P, CLOCK.AIN_N, CLOCK.AIN_P, CLOCK.CNTROUT_N, CLOCK.CNTROUT_P, CLOCK.OSCCLK_N, CLOCK.OSCCLK_P, CLOCK.SYNC_N, CLOCK.SYNC_P, DAC_REF.DOUT0_N, DAC_REF.DOUT0_P, DAC_REF.DOUT1_N, DAC_REF.DOUT1_P, DAC_REF.DSCLK_N, DAC_REF.DSCLK_P, DAC_REF.DSYNC_N, DAC_REF.DSYNC_P, DAC_REF.INVSYNC_N, DAC_REF.INVSYNC_P, DAC_REF.REFCLK_N, DAC_REF.REFCLK_P, PCIE.PCIE_CLK_N, PCIE.PCIE_CLK_P, PCIE.PCIE_RX0_N, PCIE.PCIE_RX0_P, PCIE.PCIE_TX0_N, PCIE.PCIE_TX0_P, POWER.PWRSYNC_N, POWER.PWRSYNC_P, S1_16.S1_N, S1_16.S1_P, S1_16.S2_N, S1_16.S2_P, S1_16.S3_N, S1_16.S3_P, S1_16.S4_N, S1_16.S4_P, S1_16.S5_N, S1_16.S5_P, S1_16.S6_N, S1_16.S6_P, S1_16.S7_N, S1_16.S7_P, S1_16.S8_N, S1_16.S8_P, S1_16.S9_N, S1_16.S9_P, S10_N, S10_P, S11_N, S11_P, S12_N, S12_P, S13_N, S13_P, S14_N, S14_P, S15_N, S15_P, S16_N, S16_P, S17_32.S17_N, S17_32.S17_P, S17_32.S18_N, S17_32.S18_P, S17_32.S19_N, S17_32.S19_P, S17_32.S20_N, S17_32.S20_P, S17_32.S21_N, S17_32.S21_P, S17_32.S22_N, S17_32.S22_P, S17_32.S23_N, S17_32.S23_P, S17_32.S24_N, S17_32.S24_P, S17_32.S25_N, S17_32.S25_P, S17_32.S26_N, S17_32.S26_P, S17_32.S27_N, S17_32.S27_P, S17_32.S28_N, S17_32.S28_P, S17_32.S29_N, S17_32.S29_P, S17_32.S30_N, S17_32.S30_P, S17_32.S31_N, S17_32.S31_P, S17_32.S32_N, S17_32.S32_P, S33_48.S33_N, S33_48.S33_P, S33_48.S34_N, S33_48.S34_P, S33_48.S35_N, S33_48.S35_P, S33_48.S36_N, S33_48.S36_P, S33_48.S37_N, S33_48.S37_P, S33_48.S38_N, S33_48.S38_P, S33_48.S39_N, S33_48.S39_P, S33_48.S40_N, S33_48.S40_P, S33_48.S41_N, S33_48.S41_P, S33_48.S42_N, S33_48.S42_P, S33_48.S43_N, S33_48.S43_P, S33_48.S44_N, S33_48.S44_P, S33_48.S45_N, S33_48.S45_P, S33_48.S46_N, S33_48.S46_P, S33_48.S47_N, S33_48.S47_P, S33_48.S48_N, S33_48.S48_P, S49_64.S49_N, S49_64.S49_P, S49_64.S50_N, S49_64.S50_P, S49_64.S51_N, S49_64.S51_P, S49_64.S52_N, S49_64.S52_P, S49_64.S53_N, S49_64.S53_P, S49_64.S54_N, S49_64.S54_P, S49_64.S55_N, S49_64.S55_P, S49_64.S56_N, S49_64.S56_P, S49_64.S57_N, S49_64.S57_P, S49_64.S58_N, S49_64.S58_P, S49_64.S59_N, S49_64.S59_P, S49_64.S60_N, S49_64.S60_P, S49_64.S61_N, S49_64.S61_P, S49_64.S62_N, S49_64.S62_P, S49_64.S63_N, S49_64.S63_P, S49_64.S64_N, S49_64.S64_P, SFPIN.SYNCIN_N, SFPIN.SYNCIN_P, SFPIN.SYNCOUT_N, SFPIN.SYNCOUT_P, T1_11.T1_N, T1_11.T1_P, T1_11.T2_N, T1_11.T2_P, T1_11.T3_N, T1_11.T3_P, T1_11.T4_N, T1_11.T4_P, T1_11.T5_N, T1_11.T5_P, T1_11.T6_N, T1_11.T6_P, T1_11.T7_N, T1_11.T7_P, T1_11.T8_N, T1_11.T8_P, T1_11.T9_N, T1_11.T9_P, T10_N, T10_P, T11_N, T11_P

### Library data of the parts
R145 = ChipRes1: R0603 100; Part Number: RR08P100DCT-ND; Tolerance: 0.1%
U16 = CMP-0383-00019-1: Artix-7 FPGA, 250 User I/Os, 4 GTP, 484-Ball BGA, Speed Grade 2, Commercial Grade, Pb-Free

## Sheet ChassisTimingInterfacePCIE_HL.SchDoc: PCIe Interface
size B; Engineer: Daniel Sigg; DocumentNumber: 1; Revision: C; SheetNumber: 11; SheetTotal: 12; PageSetup: Record=PageOptions¦CenterHorizontal=True¦CenterVertical=True¦PrintScale=0.72¦XCorrection=1.00¦YCorrection=1.00¦PrintKind=0¦BorderSize=5000000¦LeftOffset=0¦BottomOffset=0¦Orientation=2¦PaperLength=1000¦PaperWidth=1000¦Scale=100¦PaperSource=7¦PrintQuality=-4¦MediaType=1¦DitherType=10¦PaperKind=Tabloid¦PrintScaleMode=1
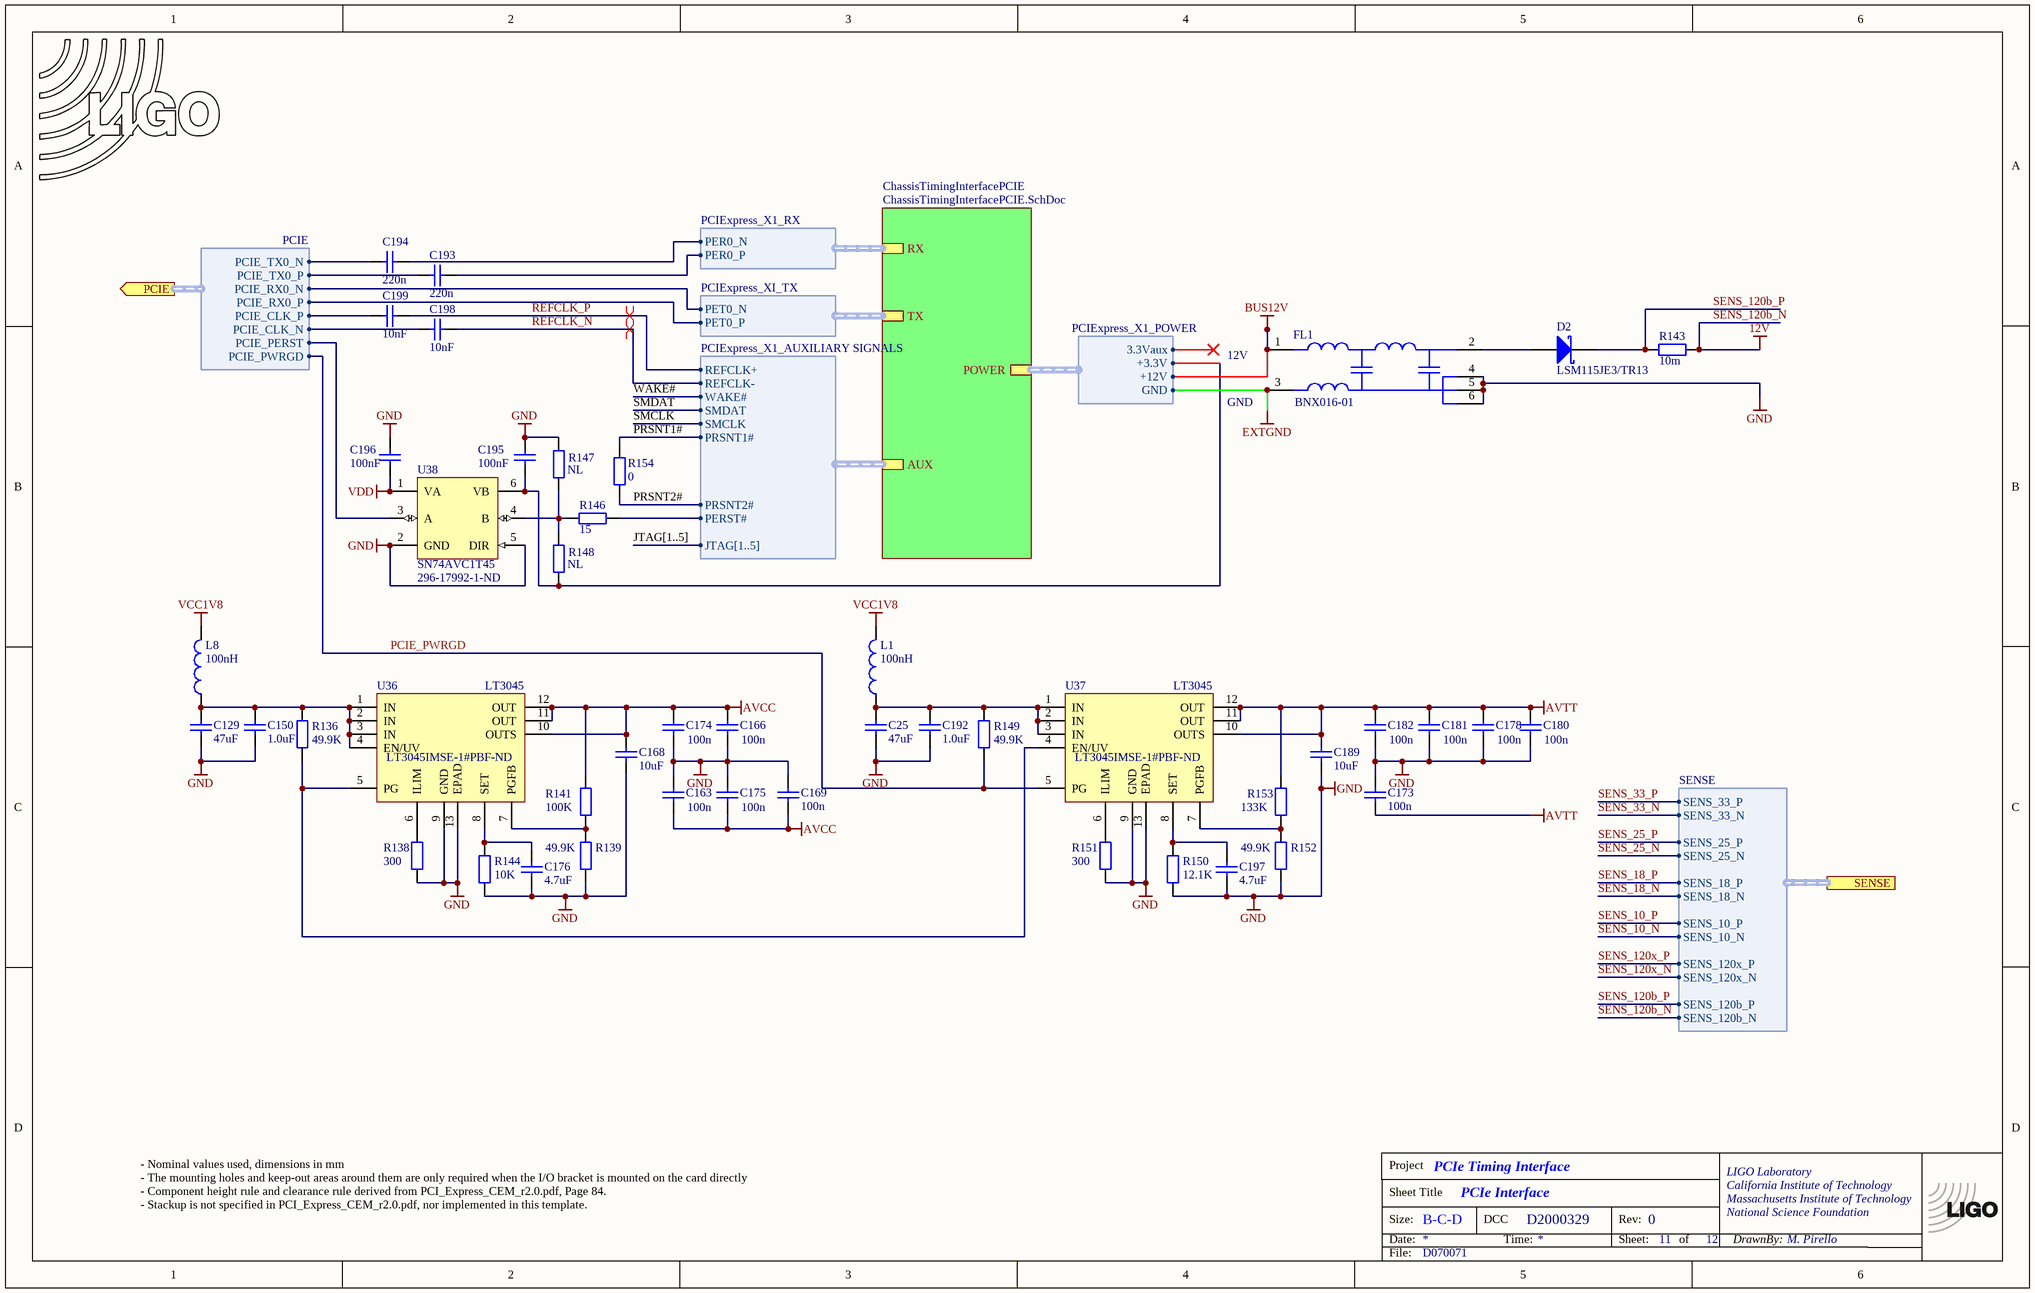
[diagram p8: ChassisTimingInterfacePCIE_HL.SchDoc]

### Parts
(Parts that share a designator on the sheet are numbered #1, #2 ... from top to bottom, then left to right.)
*?#5  TitleBlock  (value not drawn)  (graphical)
C25  47uF  [CC3216-1206]
C129  47uF  [CC3216-1206]
C150  1.0uF  [CC1608-0603]
C163  100n  [CAPC0603X33X15NL03T05]
C166  100n  [CAPC0603X33X15NL03T05]
C168  10uF  [CC2013-0805]
C169  100n  [CAPC0603X33X15NL03T05]
C173  100n  [CAPC0603X33X15NL03T05]
C174  100n  [CAPC0603X33X15NL03T05]
C175  100n  [CAPC0603X33X15NL03T05]
C176  4.7uF  [CC1608-0603]
C178  100n  [CAPC0603X33X15NL03T05]
C180  100n  [CAPC0603X33X15NL03T05]
C181  100n  [CAPC0603X33X15NL03T05]
C182  100n  [CAPC0603X33X15NL03T05]
C189  10uF  [CC2013-0805]
C192  1.0uF  [CC1608-0603]
C193  220n  [CC1005-0402]
C194  220n  [CC1005-0402]
C195  100nF  [CC1005-0402]
C196  100nF  [CC1005-0402]
C197  4.7uF  [CC1608-0603]
C198  10nF  [CC1005-0402]
C199  10nF  [CC1005-0402]
D2  LSM115JE3/TR13  [MCSM-DO-214BA-2_L]
FL1  BNX016-01  [MURA-BNX016-01_V]
L1  100nH  [CL2520-1008]
L8  100nH  [CL2520-1008]
LOGO?#1  LIGO logo  [LIGO_LOGO]  (value not drawn)  (graphical)
R136  49.9K  [CR1005-0402]
R138  300  [CR1005-0402]
R139  49.9K  [CR1005-0402]
R141  100K  [CR1005-0402]
R143  10m  [CC3216-1206]
R144  10K  [CR1005-0402]
R146  15  [CR1005-0402]
R147  NL  [CR1005-0402]
R148  NL  [CR1005-0402]
R149  49.9K  [CR1005-0402]
R150  12.1K  [CR1005-0402]
R151  300  [CR1005-0402]
R152  49.9K  [CR1005-0402]
R153  133K  [CR1005-0402]
R154  0  [CR1005-0402]
U36  LT3045  Supplier Part Number 1: LT3045IMSE-1#PBF-ND  [MSOP12_PAD]
U37  LT3045  Supplier Part Number 1: LT3045IMSE-1#PBF-ND  [MSOP12_PAD]
U38  SN74AVC1T45  Supplier Part Number 1: 296-17992-1-ND  [SC70]

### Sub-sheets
ChassisTimingInterfacePCIE = ChassisTimingInterfacePCIE.SchDoc: RX (harness PCIExpress_X1_RX), TX (harness PCIExpress_XI_TX), AUX (harness PCIExpress_X1_AUXILIARY SIGNALS), POWER (harness PCIExpress_X1_POWER)

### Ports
PCIE (out, harness PCIE), SENSE (harness SENSE)

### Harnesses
PCIExpress_X1_RX: PER0_N, PER0_P
PCIE: PCIE_CLK_N, PCIE_CLK_P, PCIE_RX0_N, PCIE_RX0_P, PCIE_TX0_N, PCIE_TX0_P, PCIE_PERST, PCIE_PWRGD
PCIExpress_XI_TX: PET0_N, PET0_P
PCIExpress_X1_POWER: +3.3V, +12V, GND, 3.3Vaux
PCIExpress_X1_AUXILIARY SIGNALS: JTAG[1..5], PERST#, PRSNT1#, PRSNT2#, REFCLK+, REFCLK-, SMCLK, SMDAT, WAKE#
SENSE: SENS_33_P, SENS_33_N, SENS_25_P, SENS_25_N, SENS_18_P, SENS_18_N, SENS_10_P, SENS_10_N, SENS_120x_P, SENS_120x_N, SENS_120b_P, SENS_120b_N

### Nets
12V: R143.2 ; port SENSE.SENS_120x_N, port SENSE.SENS_120b_N  [also labelled SENS_120b_N, SENS_120x_N]
AVCC: C163.1 C166.2 C168.2 C169.1 C174.2 C175.1 R141.2 U36.10(OUTS) U36.11(OUT) U36.12(OUT)
AVTT: C173.1 C178.2 C180.2 C181.2 C182.2 C189.2 R153.2 U37.10(OUTS) U37.11(OUT) U37.12(OUT)
BUS12V: FL1.1(B) ; sheet ChassisTimingInterfacePCIE/POWER.+12V
GND: C25.1 C129.1 C150.1 C163.2 C166.1 C168.1 C169.2 C173.2 C174.1 C175.2 C176.1 C178.1 C180.1 C181.1 C182.1 C189.1 C192.1 C195.2 C196.2 C197.1 FL1.3(PSG) FL1.4(CG) FL1.5(CG) FL1.6(CG) R138.1 R139.1 R144.1 R147.1 R150.1 R151.1 R152.1 U36.9(GND) U36.13(EPAD) U37.9(GND) U37.13(EPAD) U38.2(GND) U38.5(DIR) ; sheet ChassisTimingInterfacePCIE/POWER.GND  [also labelled EXTGND]
VCC1V8: L1.2 L8.2 ; port SENSE.SENS_18_N  [also labelled SENS_18_N]
VDD: C196.1 U38.1(VA) ; port SENSE.SENS_25_N  [also labelled SENS_25_N]
+3.3V: C195.1 R148.2 U38.6(VB) ; sheet ChassisTimingInterfacePCIE/POWER.+3.3V
PCIE.PCIE_CLK_N: C198.2 ; port PCIE.PCIE_CLK_N
PCIE.PCIE_CLK_P: C199.2 ; port PCIE.PCIE_CLK_P
PCIE.PCIE_PERST: U38.3(A) ; port PCIE.PCIE_PERST
PCIE.PCIE_RX0_N: port PCIE.PCIE_RX0_N, sheet ChassisTimingInterfacePCIE/TX.PET0_N
PCIE.PCIE_RX0_P: port PCIE.PCIE_RX0_P, sheet ChassisTimingInterfacePCIE/TX.PET0_P
PCIE.PCIE_TX0_N: C194.2 ; port PCIE.PCIE_TX0_N
PCIE.PCIE_TX0_P: C193.2 ; port PCIE.PCIE_TX0_P
PCIE_PWRGD: R149.1 U37.5(PG) ; port PCIE.PCIE_PWRGD  [project net PCIE.PCIE_PWRGD]
PER0_N: C193.1 ; sheet ChassisTimingInterfacePCIE/RX.PER0_P
PER0_P: C194.1 ; sheet ChassisTimingInterfacePCIE/RX.PER0_N
PERST#: R146.1 ; sheet ChassisTimingInterfacePCIE/AUX.PERST#
PRSNT1#: R154.2 ; sheet ChassisTimingInterfacePCIE/AUX.PRSNT1#
PRSNT2#: R154.1 ; sheet ChassisTimingInterfacePCIE/AUX.PRSNT2#
REFCLK_N: C198.1 ; sheet ChassisTimingInterfacePCIE/AUX.REFCLK-
REFCLK_P: C199.1 ; sheet ChassisTimingInterfacePCIE/AUX.REFCLK+
SENS_120b_P: D2.2(K) R143.1 ; port SENSE.SENS_120b_P  [project net SENSE.SENS_120b_P]
NetC25_2: C25.2 C192.2 L1.1 R149.2 U37.1(IN) U37.2(IN) U37.3(IN)
NetC129_2: C129.2 C150.2 L8.1 R136.2 U36.1(IN) U36.2(IN) U36.3(IN) U36.4(EN/UV)
NetC176_2: C176.2 R144.2 U36.8(SET)
NetC197_2: C197.2 R150.2 U37.8(SET)
NetD2_1: D2.1(A) FL1.2(CB)
NetR136_1: R136.1 U36.5(PG) U37.4(EN/UV)
NetR138_2: R138.2 U36.6(ILIM)
NetR139_2: R139.2 R141.1 U36.7(PGFB)
NetR146_2: R146.2 R147.2 R148.1 U38.4(B)
NetR151_2: R151.2 U37.6(ILIM)
NetR152_2: R152.2 R153.1 U37.7(PGFB)

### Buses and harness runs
bus JTAG[1..5]

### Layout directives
differential pair: REFCLK_N, REFCLK_P

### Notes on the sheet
- (near FL1) 12V
- (near FL1) GND
- - Nominal values used, dimensions in mm
  - The mounting holes and keep-out areas around them are only required when the I/O bracket is mounted on the card directly
  - Component height rule and clearance rule derived from PCI_Express_CEM_r2.0.pdf, Page 84.
  - Stackup is not specified in PCI_Express_CEM_r2.0.pdf, nor implemented in this template.

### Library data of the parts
C25 C129 = ChipCap: C1206 47uF; Part Number: 490-16268-1-ND; Tolerance: 10%
C150 C192 = ChipCap: C0603 1.0uF; Part Number: 1276-1184-1-ND; Tolerance: 10%
C163 C166 C169 C173-C175 C178 C180-C182 = CMP-2010-00306-1: C0201 0.1uF; Part Number: CL03A474MR3NNNC; Tolerance: 10%
C168 C189 = ChipCap: C0805 10uF; Part Number: 1276-6454-1-ND; Tolerance: 10%
C176 C197 = ChipCap: C0603 4.7uF; Part Number: 1276-2087-1-ND; Tolerance: 10%
C193 C194 = ChipCap: C0402 0.22uF; Part Number: 587-6021-1-ND; Tolerance: 10%
C195 C196 = ChipCap: C0402 0.1uF; Part Number: 1276-6720-1-ND; Tolerance: 10%
C198 C199 = ChipCap: C0402 0.01uF; Part Number: 311-1349-1-ND; Tolerance: 10%
D2 = CMP-2000-06604-1: Ultra Low Forward Voltage Schottky Rectifier, 15 V, -55 to 100 degC, 2-Pin Molded, RoHS, Tape and Reel; Part Number: LSM115JE3/TR13CT-ND
FL1 = CMP-2000-05960-1: Block Type EMIFIL(R) Reference Specification, 15 A, 25 V, -40 to 125 degC, 6-Pin THD, RoHS, Bulk; Part Number: 490-5055-ND
L1 L8 = ChipInductor: Inductor; Part Number: 994-1008CS-101XJLC
LOGO?#1 = LIGO_logo
R136 R139 R149 R152 = ChipRes1: R0402 49.9k; Part Number: RR05P49.9KDCT-ND; Tolerance: 0.1%
R138 R151 = ChipRes1: R0402 300; Part Number: RR05P300DCT-ND; Tolerance: 0.1%
R141 = ChipRes1: R0402 100k; Part Number: RR05P100KDCT-ND; Tolerance: 0.1%
R143 = ChipRes1: R1206 10m; Part Number: 273-PCS1206DR0100ETCT-ND; Tolerance: 0.1%
R144 = ChipRes1: R0402 10k; Part Number: RR05P10.0KDCT-ND; Tolerance: 0.1%
R146 = ChipRes1: R0402 15; Part Number: A127144CT-ND; Tolerance: 0.1%
R147 R148 = ChipRes1: Resistor, surface mount; Tolerance: 0.1%
R150 = ChipRes1: R0402 12.1k; Part Number: RR05P12.1KDCT-ND; Tolerance: 0.1%
R153 = ChipRes1: R0402 133k; Part Number: A127523CT-ND; Tolerance: 0.1%
R154 = ChipRes1: R0402 0; Part Number: 541-2877-1-ND; Tolerance: 0.1%
U36 U37 = LT3045: 20V, 500mA, Ultralow Noise, / Ultrahigh PSRR Linear Regulator
U38 = SN74LVC1T45: Single-Bit Dual Supply Transceiver

## Sheet ChassisTimingInterfacePCIE.SchDoc: PCIe
size B; Engineer: Daniel Sigg; DocumentNumber: 1; Revision: C; SheetNumber: 12; SheetTotal: 12; PageSetup: Record=PageOptions¦CenterHorizontal=True¦CenterVertical=True¦PrintScale=0.72¦XCorrection=1.00¦YCorrection=1.00¦PrintKind=0¦BorderSize=5000000¦LeftOffset=0¦BottomOffset=0¦Orientation=2¦PaperLength=1000¦PaperWidth=1000¦Scale=100¦PaperSource=7¦PrintQuality=-4¦MediaType=1¦DitherType=10¦PaperKind=Tabloid¦PrintScaleMode=1
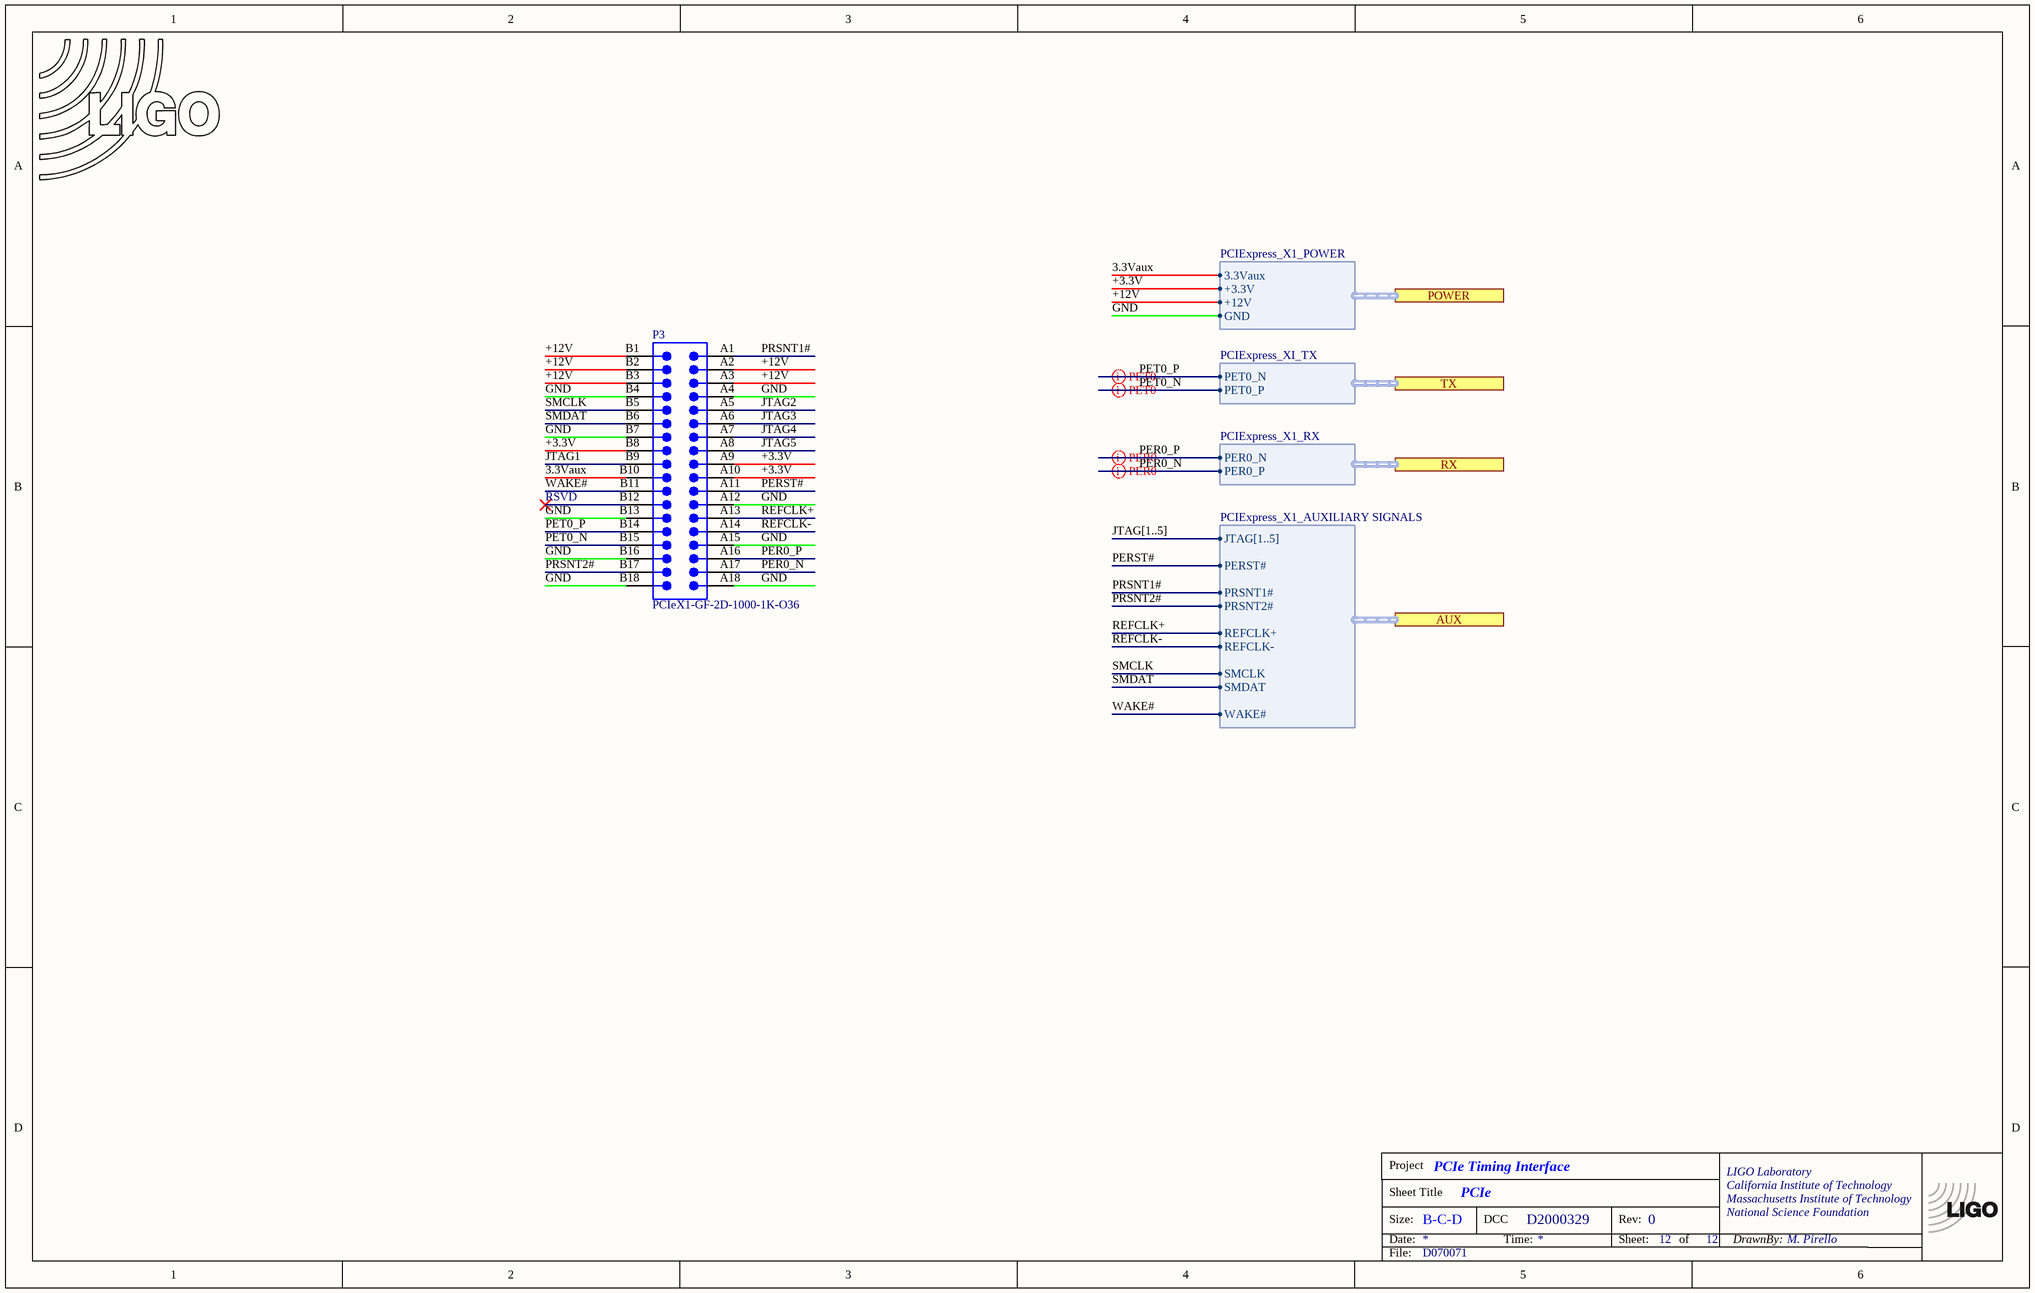
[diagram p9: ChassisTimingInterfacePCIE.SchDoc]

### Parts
(Parts that share a designator on the sheet are numbered #1, #2 ... from top to bottom, then left to right.)
*?#6  TitleBlock  (value not drawn)  (graphical)
LOGO?#2  LIGO logo  [LIGO_LOGO]  (value not drawn)  (graphical)
P3  PCIeX1-GF-2D-1000-1K-O36  [PCIeX1-GF-2D-1000-1K-O36]  (no BOM)

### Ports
AUX (harness PCIExpress_X1_AUXILIARY SIGNALS), POWER (harness PCIExpress_X1_POWER), RX (harness PCIExpress_X1_RX), TX (harness PCIExpress_XI_TX)

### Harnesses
PCIExpress_X1_POWER: +3.3V, +12V, GND, 3.3Vaux
PCIExpress_XI_TX: PET0_N, PET0_P
PCIExpress_X1_RX: PER0_N, PER0_P
PCIExpress_X1_AUXILIARY SIGNALS: JTAG[1..5], PERST#, PRSNT1#, PRSNT2#, REFCLK+, REFCLK-, SMCLK, SMDAT, WAKE#

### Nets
+12V: P3.A2 P3.A3 P3.B1 P3.B2 P3.B3 ; port POWER.+12V  [project net BUS12V]
GND: P3.A4 P3.A12 P3.A15 P3.A18 P3.B4 P3.B7 P3.B13 P3.B16 P3.B18 ; port POWER.GND
3.3Vaux: P3.B10 ; port POWER.3.3Vaux
+3.3V: P3.A9 P3.A10 P3.B8 ; port POWER.+3.3V
JTAG1: P3.B9
JTAG2: P3.A5
JTAG3: P3.A6
JTAG4: P3.A7
JTAG5: P3.A8
PER0_N: P3.A17 ; port RX.PER0_P
PER0_P: P3.A16 ; port RX.PER0_N
PERST#: P3.A11 ; port AUX.PERST#
PET0_N: P3.B15 ; port TX.PET0_P  [project net PCIE.PCIE_RX0_P]
PET0_P: P3.B14 ; port TX.PET0_N  [project net PCIE.PCIE_RX0_N]
PRSNT1#: P3.A1 ; port AUX.PRSNT1#
PRSNT2#: P3.B17 ; port AUX.PRSNT2#
REFCLK+: P3.A13 ; port AUX.REFCLK+  [project net REFCLK_P]
REFCLK-: P3.A14 ; port AUX.REFCLK-  [project net REFCLK_N]
SMCLK: P3.B5 ; port AUX.SMCLK
SMDAT: P3.B6 ; port AUX.SMDAT
WAKE#: P3.B11 ; port AUX.WAKE#

Not connected (* = marked no-connect by the designer): P3 B12*

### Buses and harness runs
bus JTAG[1..5]

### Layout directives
differential pair: PCIE.PCIE_RX0_N, PCIE.PCIE_RX0_P, PER0_N, PER0_P

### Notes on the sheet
- RSVD

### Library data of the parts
LOGO?#2 = LIGO_logo
P3 = CMP-0001-00030-1: Golden finger, PCIeX1, Dual, Opposite, Pitch 1mm, 36-Position

## Sheet ChassisTimingInterface6.SchDoc: Duotone
size B; Author: M. Pirello; Organization: LIGO Laboratory; Address1: California Institute of Technology; Address2: Massachusetts Institute of Technology; Address3: National Science Foundation; Address4: Australia 2086; DocumentNumber: 8; SheetNumber: 7; SheetTotal: 12; Size: B
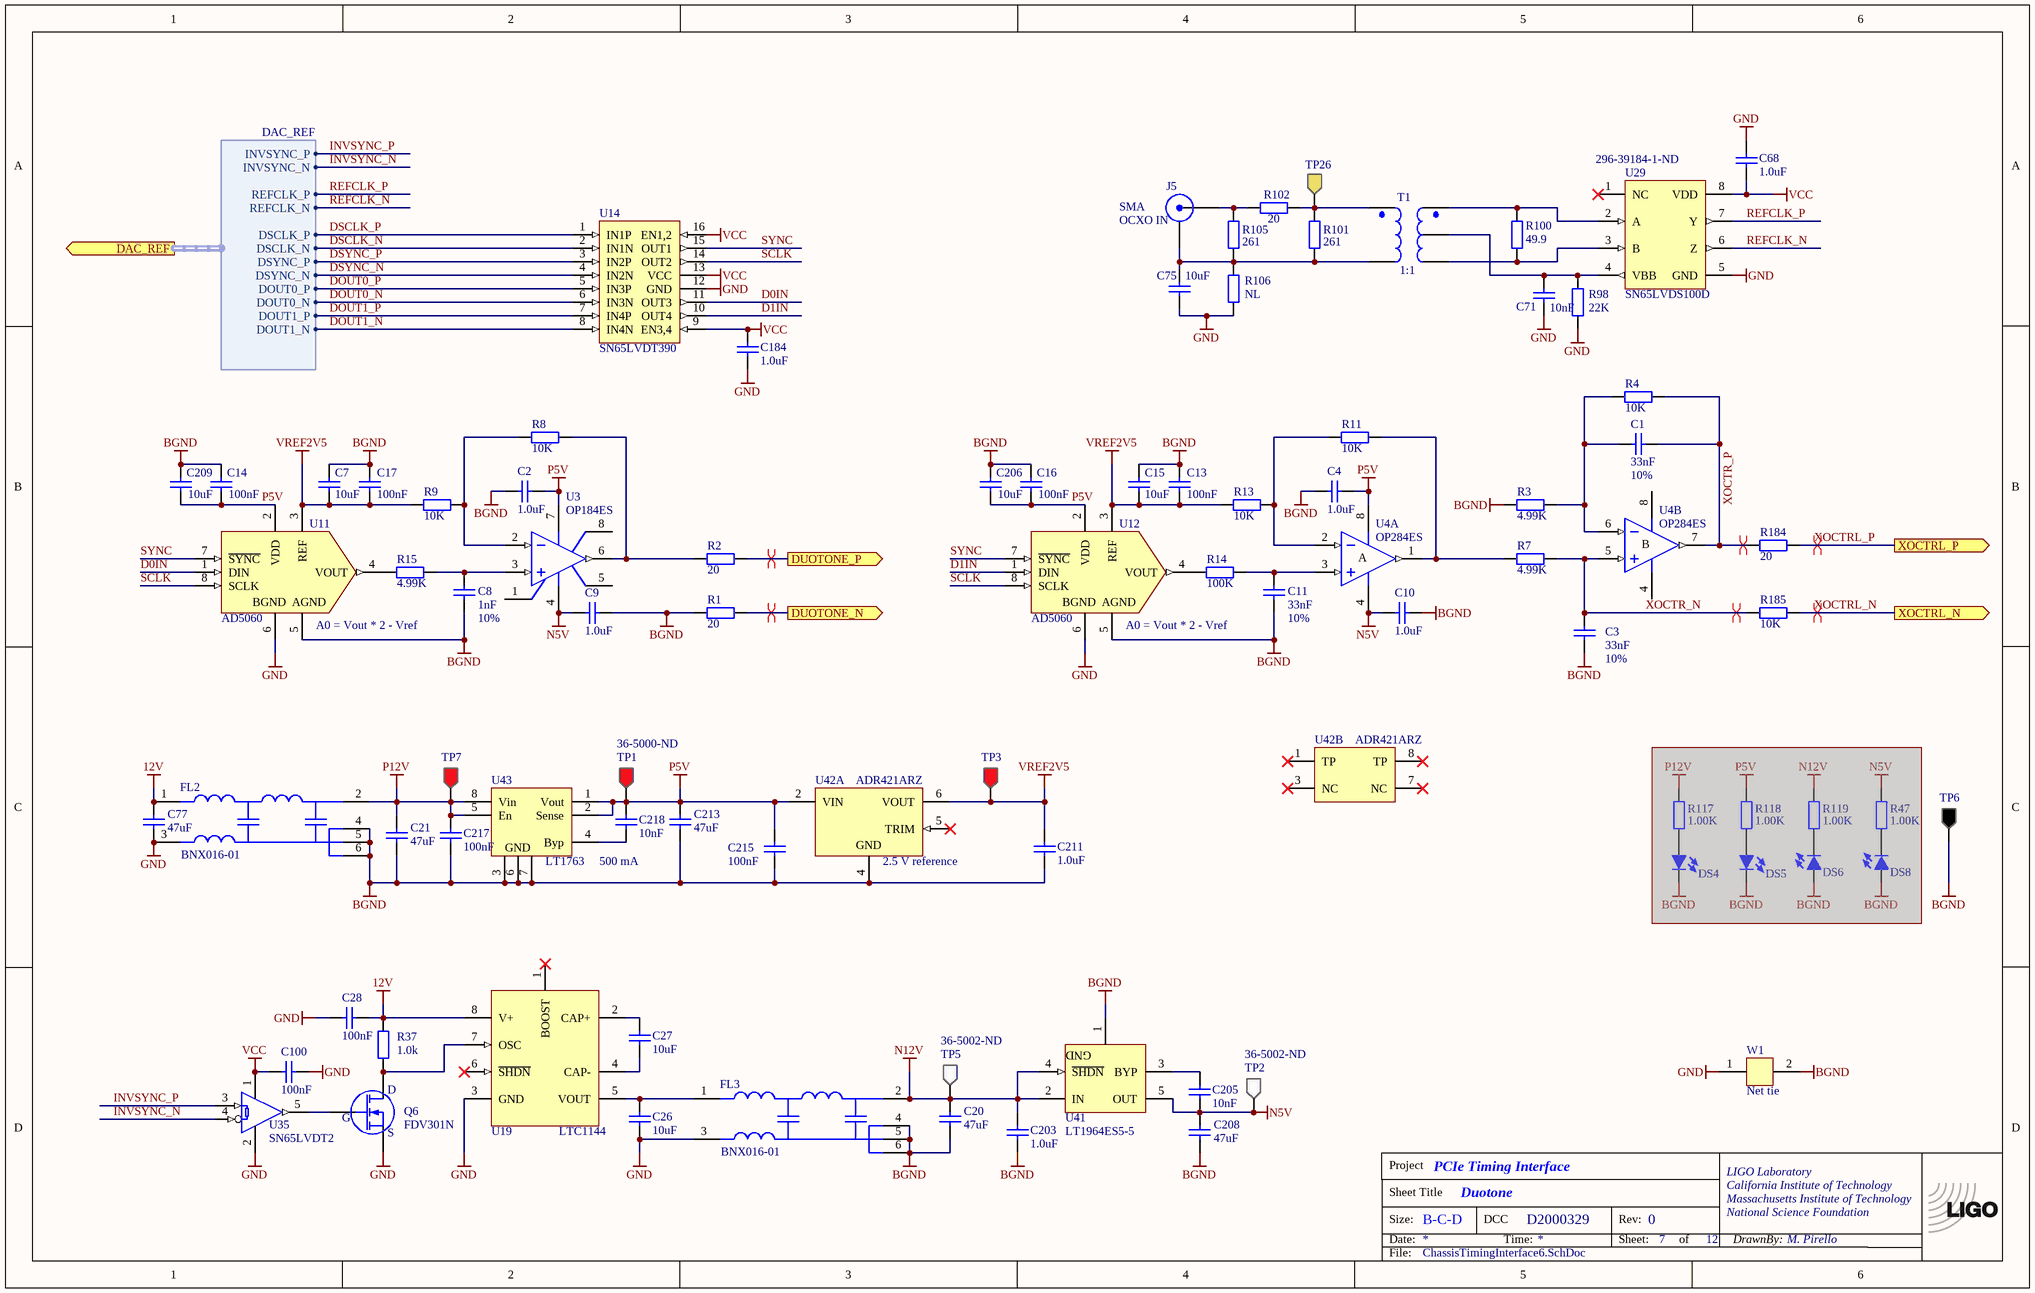
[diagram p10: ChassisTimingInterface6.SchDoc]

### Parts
(Parts that share a designator on the sheet are numbered #1, #2 ... from top to bottom, then left to right.)
*?#7  TitleBlock  (value not drawn)  (graphical)
?#1  (no value)  (no BOM)
C1  Tolerance: 10%  [CC1005-0402]  (hidden comment: 33nF)
C2  1.0uF  [CC1608-0603]
C3  Tolerance: 10%  [CC1005-0402]  (hidden comment: 33nF)
C4  1.0uF  [CC1608-0603]
C7  10uF  [CC2013-0805]
C8  Tolerance: 10%  [CC1005-0402]  (hidden comment: 1nF)
C9  1.0uF  [CC1608-0603]
C10  1.0uF  [CC1608-0603]
C11  Tolerance: 10%  [CC1005-0402]  (hidden comment: 33nF)
C13  100nF  [CC1005-0402]
C14  100nF  [CC1005-0402]
C15  10uF  [CC2013-0805]
C16  100nF  [CC1005-0402]
C17  100nF  [CC1005-0402]
C20  47uF  [CC3216-1206]
C21  47uF  [CC3216-1206]
C26  10uF  [CC2013-0805]
C27  10uF  [CC2013-0805]
C28  100nF  [CC1005-0402]
C68  1.0uF  [CC1608-0603]
C71  10nF  [CC1005-0402]
C75  10uF  [CC2013-0805]
C77  47uF  [CC3216-1206]
C100  100nF  [CC1005-0402]
C184  1.0uF  [CC1608-0603]
C203  1.0uF  [CC1608-0603]
C205  10nF  [CC1005-0402]
C206  10uF  [CC2013-0805]
C208  47uF  [CC3216-1206]
C209  10uF  [CC2013-0805]
C211  1.0uF  [CC1608-0603]
C213  47uF  [CC3216-1206]
C215  100nF  [CC1005-0402]
C217  100nF  [CC1005-0402]
C218  10nF  [CC1005-0402]
DS4  LED  [LED-0805]  (value not drawn)  (masked out: inside a compile mask, not in the netlist)
DS5  LED  [LED-0805]  (value not drawn)  (masked out: inside a compile mask, not in the netlist)
DS6  LED  [LED-0805]  (value not drawn)  (masked out: inside a compile mask, not in the netlist)
DS8  LED  [LED-0805]  (value not drawn)  (masked out: inside a compile mask, not in the netlist)
FL2  BNX016-01  [MURA-BNX016-01_V]
FL3  BNX016-01  [MURA-BNX016-01_V]
J5  SMA  [SMA-RA]
Q6  FDV301N  [SO-G3/C2.25]
R1  20  [CR1005-0402]
R2  20  [CR1005-0402]
R3  4.99K  [CR1608-0603]
R4  10K  [CR1005-0402]
R7  4.99K  [CR1608-0603]
R8  10K  [CR1005-0402]
R9  10K  [CR1005-0402]
R11  10K  [CR1005-0402]
R13  10K  [CR1005-0402]
R14  100K  [CR1005-0402]
R15  4.99K  [CR1608-0603]
R37  1.0k  [CR1608-0603]
R47#1  1.00K  [CR2012-0805]  (masked out: inside a compile mask, not in the netlist)
R98  22K  [CR2012-0805]
R100  49.9  [CR1608-0603]
R101  261  [CR2012-0805]
R102  20  [CR1005-0402]
R105  261  [CR2012-0805]
R106  NL  [CR2012-0805]
R117#2  1.00K  [CR2012-0805]  (masked out: inside a compile mask, not in the netlist)
R118#2  1.00K  [CR2012-0805]  (masked out: inside a compile mask, not in the netlist)
R119#2  1.00K  [CR2012-0805]  (masked out: inside a compile mask, not in the netlist)
R184  20  [CR1005-0402]
R185  10K  [CR1005-0402]
T1  1:1  [AT224-3]
TP1  Supplier Part Number 1: 36-5000-ND  [TP1-RED]  (hidden comment: Testpoint)
TP2  Supplier Part Number 1: 36-5002-ND  [TP1-WHT]  (hidden comment: Testpoint)
TP3  Testpoint  [TP1-RED]  (value not drawn)
TP5  Supplier Part Number 1: 36-5002-ND  [TP1-WHT]  (hidden comment: Testpoint)
TP6  Testpoint  [TP1-BLK]  (value not drawn)
TP7  Testpoint  [TP1-RED]  (value not drawn)
TP26  Testpoint  [TP1-YLW]  (value not drawn)
U3  OP184ES  [SO-8_N]
U4  OP284ES  [SO-8_N]  (parts A,B of 2)
U11  AD5060  [SSO-G8/SM8]
U12  AD5060  [SSO-G8/SM8]
U14  SN65LVDT390  [TSSOP16]
U19  LTC1144  [SO-G8]
U29  SN65LVDS100D  Supplier Part Number 1: 296-39184-1-ND  [MSOP8]
U35  SN65LVDT2  [SO-G5/E2.4]
U41  LT1964ES5-5  [LT-S5-5-TSOT-23_M]
U42  ADR421ARZ  [ADI-R-8_M]  (parts A,B of 2)
U43  LT1763  [SO-G8]
W1  Net tie  [NETTIE1_BOTH]  (net tie, no BOM)

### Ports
DAC_REF (out, harness DAC_REF), DUOTONE_N (out), DUOTONE_P (out), XOCTRL_N (out), XOCTRL_P (out)

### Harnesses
DAC_REF: DSCLK_N, DSCLK_P, DSYNC_N, DSYNC_P, DOUT0_N, DOUT0_P, DOUT1_N, DOUT1_P, REFCLK_N, REFCLK_P, INVSYNC_N, INVSYNC_P

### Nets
12V: C28.1 C77.2 FL2.1(B) R37.2 U19.8(V+)
BGND: C2.1 C3.1 C4.1 C7.2 C8.2 C9.2 C10.2 C11.1 C13.2 C14.2 C15.2 C16.2 C17.2 C20.1 C21.1 C203.1 C206.2 C208.1 C209.2 C211.1 C213.1 C215.1 C217.1 FL2.4(CG) FL2.5(CG) FL2.6(CG) FL3.4(CG) FL3.5(CG) FL3.6(CG) R1.1 R3.1 TP6.1 U11.5(AGND) U12.5(AGND) U41.1(GND) U42.4(GND) U43.3(GND) U43.6(GND) U43.7(GND) W1.2
GND: C26.1 C28.2 C68.2 C71.1 C75.1 C77.1 C100.1 C184.1 FL2.3(PSG) FL3.3(PSG) Q6.2(S) R98.2 R106.2 U11.6(BGND) U12.6(BGND) U14.12(GND) U19.3(GND) U29.5(GND) U35.2(GND) W1.1
N5V: C9.1 C10.1 C205.1 C208.2 TP2.1 U3.4(V-) U4.4(V-) U41.5(OUT)
N12V: C20.2 C203.2 FL3.2(CB) TP5.1 U41.2(IN) U41.4(~{SHDN})
P5V: C2.2 C4.2 C14.1 C16.1 C206.1 C209.1 C213.2 C215.2 C218.2 TP1.1 U3.7(V+) U4.8(V+) U11.2(VDD) U12.2(VDD) U42.2(VIN) U43.1(Vout) U43.2(Sense)
P12V: C21.2 C217.2 FL2.2(CB) TP7.1 U43.5(En) U43.8(Vin)
VCC: C68.1 C100.2 C184.2 U14.9(EN3,4) U14.13(VCC) U14.16(EN1,2) U29.8(VDD) U35.1(VCC)
VREF2V5: C7.1 C13.1 C15.1 C17.1 C211.2 R9.1 R13.1 TP3.1 U11.3(REF) U12.3(REF) U42.6(VOUT)
D0IN: U11.1(DIN) U14.11(OUT3)
D1IN: U12.1(DIN) U14.10(OUT4)
DOUT0_N: U14.6(IN3N) ; port DAC_REF.DOUT0_N  [project net DAC_REF.DOUT0_N]
DOUT0_P: U14.5(IN3P) ; port DAC_REF.DOUT0_P  [project net DAC_REF.DOUT0_P]
DOUT1_N: U14.8(IN4N) ; port DAC_REF.DOUT1_N  [project net DAC_REF.DOUT1_N]
DOUT1_P: U14.7(IN4P) ; port DAC_REF.DOUT1_P  [project net DAC_REF.DOUT1_P]
DSCLK_N: U14.2(IN1N) ; port DAC_REF.DSCLK_N  [project net DAC_REF.DSCLK_N]
DSCLK_P: U14.1(IN1P) ; port DAC_REF.DSCLK_P  [project net DAC_REF.DSCLK_P]
DSYNC_N: U14.4(IN2N) ; port DAC_REF.DSYNC_N  [project net DAC_REF.DSYNC_N]
DSYNC_P: U14.3(IN2P) ; port DAC_REF.DSYNC_P  [project net DAC_REF.DSYNC_P]
DUOTONE_N: R1.2 ; port DUOTONE_N
DUOTONE_P: R2.2 ; port DUOTONE_P
INVSYNC_N: U35.4(B) ; port DAC_REF.INVSYNC_N  [project net DAC_REF.INVSYNC_N]
INVSYNC_P: U35.3(A) ; port DAC_REF.INVSYNC_P  [project net DAC_REF.INVSYNC_P]
REFCLK_N: U29.6(Z) ; port DAC_REF.REFCLK_N  [project net DAC_REF.REFCLK_N]
REFCLK_P: U29.7(Y) ; port DAC_REF.REFCLK_P  [project net DAC_REF.REFCLK_P]
SCLK: U11.8(SCLK) U12.8(SCLK) U14.14(OUT2)
SYNC: U11.7(~{SYNC}) U12.7(~{SYNC}) U14.15(OUT1)
XOCTR_N: C3.2 R7.2 R185.1 U4.5(IN+)
XOCTR_P: C1.1 R4.2 R184.1 U4.7(OUT)
XOCTRL_N: R185.2 ; port XOCTRL_N
XOCTRL_P: R184.2 ; port XOCTRL_P
NetC1_2: C1.2 R3.2 R4.1 U4.6(IN-)
NetC8_1: C8.1 R15.2 U3.3(IN+)
NetC11_2: C11.2 R14.2 U4.3(IN+)
NetC26_2: C26.2 FL3.1(B) U19.5(VOUT)
NetC27_1: C27.1 U19.4(CAP-)
NetC27_2: C27.2 U19.2(CAP+)
NetC71_2: C71.2 R98.1 T1.2 U29.4(VBB)
NetC75_2: C75.2 J5.2(Y) R101.1 R105.1 R106.1 T1.4
NetC205_2: C205.2 U41.3(BYP)
NetC218_1: C218.1 U43.4(Byp)
NetJ5_1: J5.1(X) R102.2 R105.2
NetQ6_1: Q6.1(G) U35.5(R)
NetQ6_3: Q6.3(D) R37.1 U19.7(OSC)
NetR2_1: R2.1 R8.2 U3.6(OUT)
NetR7_1: R7.1 R11.2 U4.1(OUT)
NetR8_1: R8.1 R9.2 U3.2(IN-)
NetR11_1: R11.1 R13.2 U4.2(IN-)
NetR14_1: R14.1 U12.4(VOUT)
NetR15_1: R15.1 U11.4(VOUT)
NetR100_1: R100.1 T1.3 U29.3(B)
NetR100_2: R100.2 T1.1 U29.2(A)
NetR101_2: R101.2 R102.1 T1.6 TP26.1

Not connected (* = marked no-connect by the designer): U3 1(NUL) 5(NUL) 8(NC); U19 1(BOOST)* 6(~{SHDN})*; U29 1(NC)*; U42 1(TP)* 3(NC)* 5(TRIM)* 7(NC)* 8(TP)*

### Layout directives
differential pair: DUOTONE_N, DUOTONE_P, XOCTR_N, XOCTR_P, XOCTRL_N, XOCTRL_P

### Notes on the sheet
- (near J5) OCXO IN
- (near U11) A0 = Vout * 2 - Vref
- (near U12) A0 = Vout * 2 - Vref
- 500 mA
- (near U42) 2.5 V reference

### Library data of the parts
?#1 = LIGO_logo: LIGO logo
C1 C3 C11 = ChipCap: C0402 0.033nF; Part Number: 490-13296-1-ND
C2 C4 C9 C10 C68 C184 C203 C211 = ChipCap: as C150 on sheet ChassisTimingInterfacePCIE_HL
C7 C15 C26 C27 C75 C206 C209 = ChipCap: as C168 on sheet ChassisTimingInterfacePCIE_HL
C8 = ChipCap: C0402 1.0nF; Part Number: 1292-1246-1-ND
C13 C14 C16 C17 C28 C100 C215 C217 = ChipCap: as C195 on sheet ChassisTimingInterfacePCIE_HL
C20 C21 C77 C208 C213 = ChipCap: as C25 on sheet ChassisTimingInterfacePCIE_HL
C71 C205 C218 = ChipCap: as C198 on sheet ChassisTimingInterfacePCIE_HL
DS4-DS6 DS8 = LED: Panel mount LED
FL2 FL3 = CMP-2000-05960-1: as FL1 on sheet ChassisTimingInterfacePCIE_HL
J5 = SMA: SMA, PCB Mount, Right Angle; Part Number: 2057-RF2-49B-T-00-50-G-HDW-ND
Q6 = FDV301N: FDV301N, Digital FET, N-channel, SOT23; Part Number: FDV301NCT-ND
R1 R2 R102 R184 = ChipRes1: R0402 20; Part Number: A127156CT-ND; Tolerance: 0.1%
R3 R7 R15 = ChipRes1: R0603 4.99k; Part Number: RR08P4.99KDCT-ND; Tolerance: 0.1%
R4 R8 R9 R11 R13 R185 = ChipRes1: as R144 on sheet ChassisTimingInterfacePCIE_HL
R14 = ChipRes1: as R141 on sheet ChassisTimingInterfacePCIE_HL
R37 = ChipRes1: R0603 1.0k; Part Number: RR08P1.0KDCT-ND; Tolerance: 0.1%
R47#1 R117#2 R118#2 R119#2 = ChipRes1: Resistor, surface mount; Tolerance: 1%
R98 = ChipRes1: R0805 22k; Part Number: RR12P22.0KDCT-ND; Tolerance: 0.1%
R100 = ChipRes1: R0603 49.9; Part Number: RR08Q49.9DCT-ND; Tolerance: 0.1%
R101 R105 = ChipRes1: R0805 261; Part Number: P20214CT-ND; Tolerance: 0.1%
R106 = ChipRes1: Resistor, surface mount; Tolerance: 0.1%
T1 = TC1.5-52: Transformer 1:4, wide band, 0.5-300 MHz; Part Number: TC1.5-52T
TP1 = TP_POSITIVE: Testpoint, red
TP2 TP5 = TP_NEGATIVE: Testpoint, white
TP3 TP7 = TP_POSITIVE: Testpoint, red; Part Number: 36-5000-ND
TP6 = TP_GND: Testpoint, black; Part Number: 36-5001-ND
TP26 = TP_SIGNAL: Testpoint, yellow; Part Number: 36-5004-ND
U3 = OP184ES: Precision Rail-to-Rail Input and Ouput Operational Amplifier; Part Number: OP184FSZ-REELCT-ND
U4 = OP284ES: Precision Rail-to-Rail Input and Output Operational Amplifier; Part Number: OP284ESZ-REEL7TR-ND
U11 U12 = AD5060: 16 bit DAC, 250kSPS, unipolar, serial; Part Number: AD5060BRJZ-1500RL7CT-ND
U14 = SN65LVDT390: Quad LVDS Receiver with 100 Ohm termination; Part Number: 296-6901-5-ND
U19 = LTC1144: Switched capacitor voltage inverter; Part Number: LTC1144IS8#TRPBFCT-ND
U29 = SN65LVDS100: DIFF TRANSLATOR
U35 = SN65LVDT2DBV: Single LVDS Receiver with 100 Ohm termination; Part Number: 296-6896-1-ND
U41 = CMP-0476-01338-1: 200 mA, Low Noise, Low Dropout Negative Micropower Regulator, -1.9 to -20 V Vin, -5 V Vout, 5-pin SOT23 (S5-5), -40 to 125 degC, Pb-Free, Mini Tape and Reel; Part Number: LT1964ES5-5#TRPBFCT-ND
U42 = CMP-0784-00214-1: Ultraprecision, Low Noise, XFET(R) Voltage Reference, 2.5 V Output, 4.5 to 18 V Supply, Industrial, 8-pin SOIC (R-8), Tube; Part Number: ADR421ARZ-REEL7CT-ND
U43 = LT1763: Positive voltage regulator; Part Number: LT1763CS8#PBF-ND
W1 = NetTie1: Tie two nets together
